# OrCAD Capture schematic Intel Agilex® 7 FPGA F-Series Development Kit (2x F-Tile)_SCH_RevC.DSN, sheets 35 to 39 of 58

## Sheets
35 PG38 I2C TRANSLATORS: size C
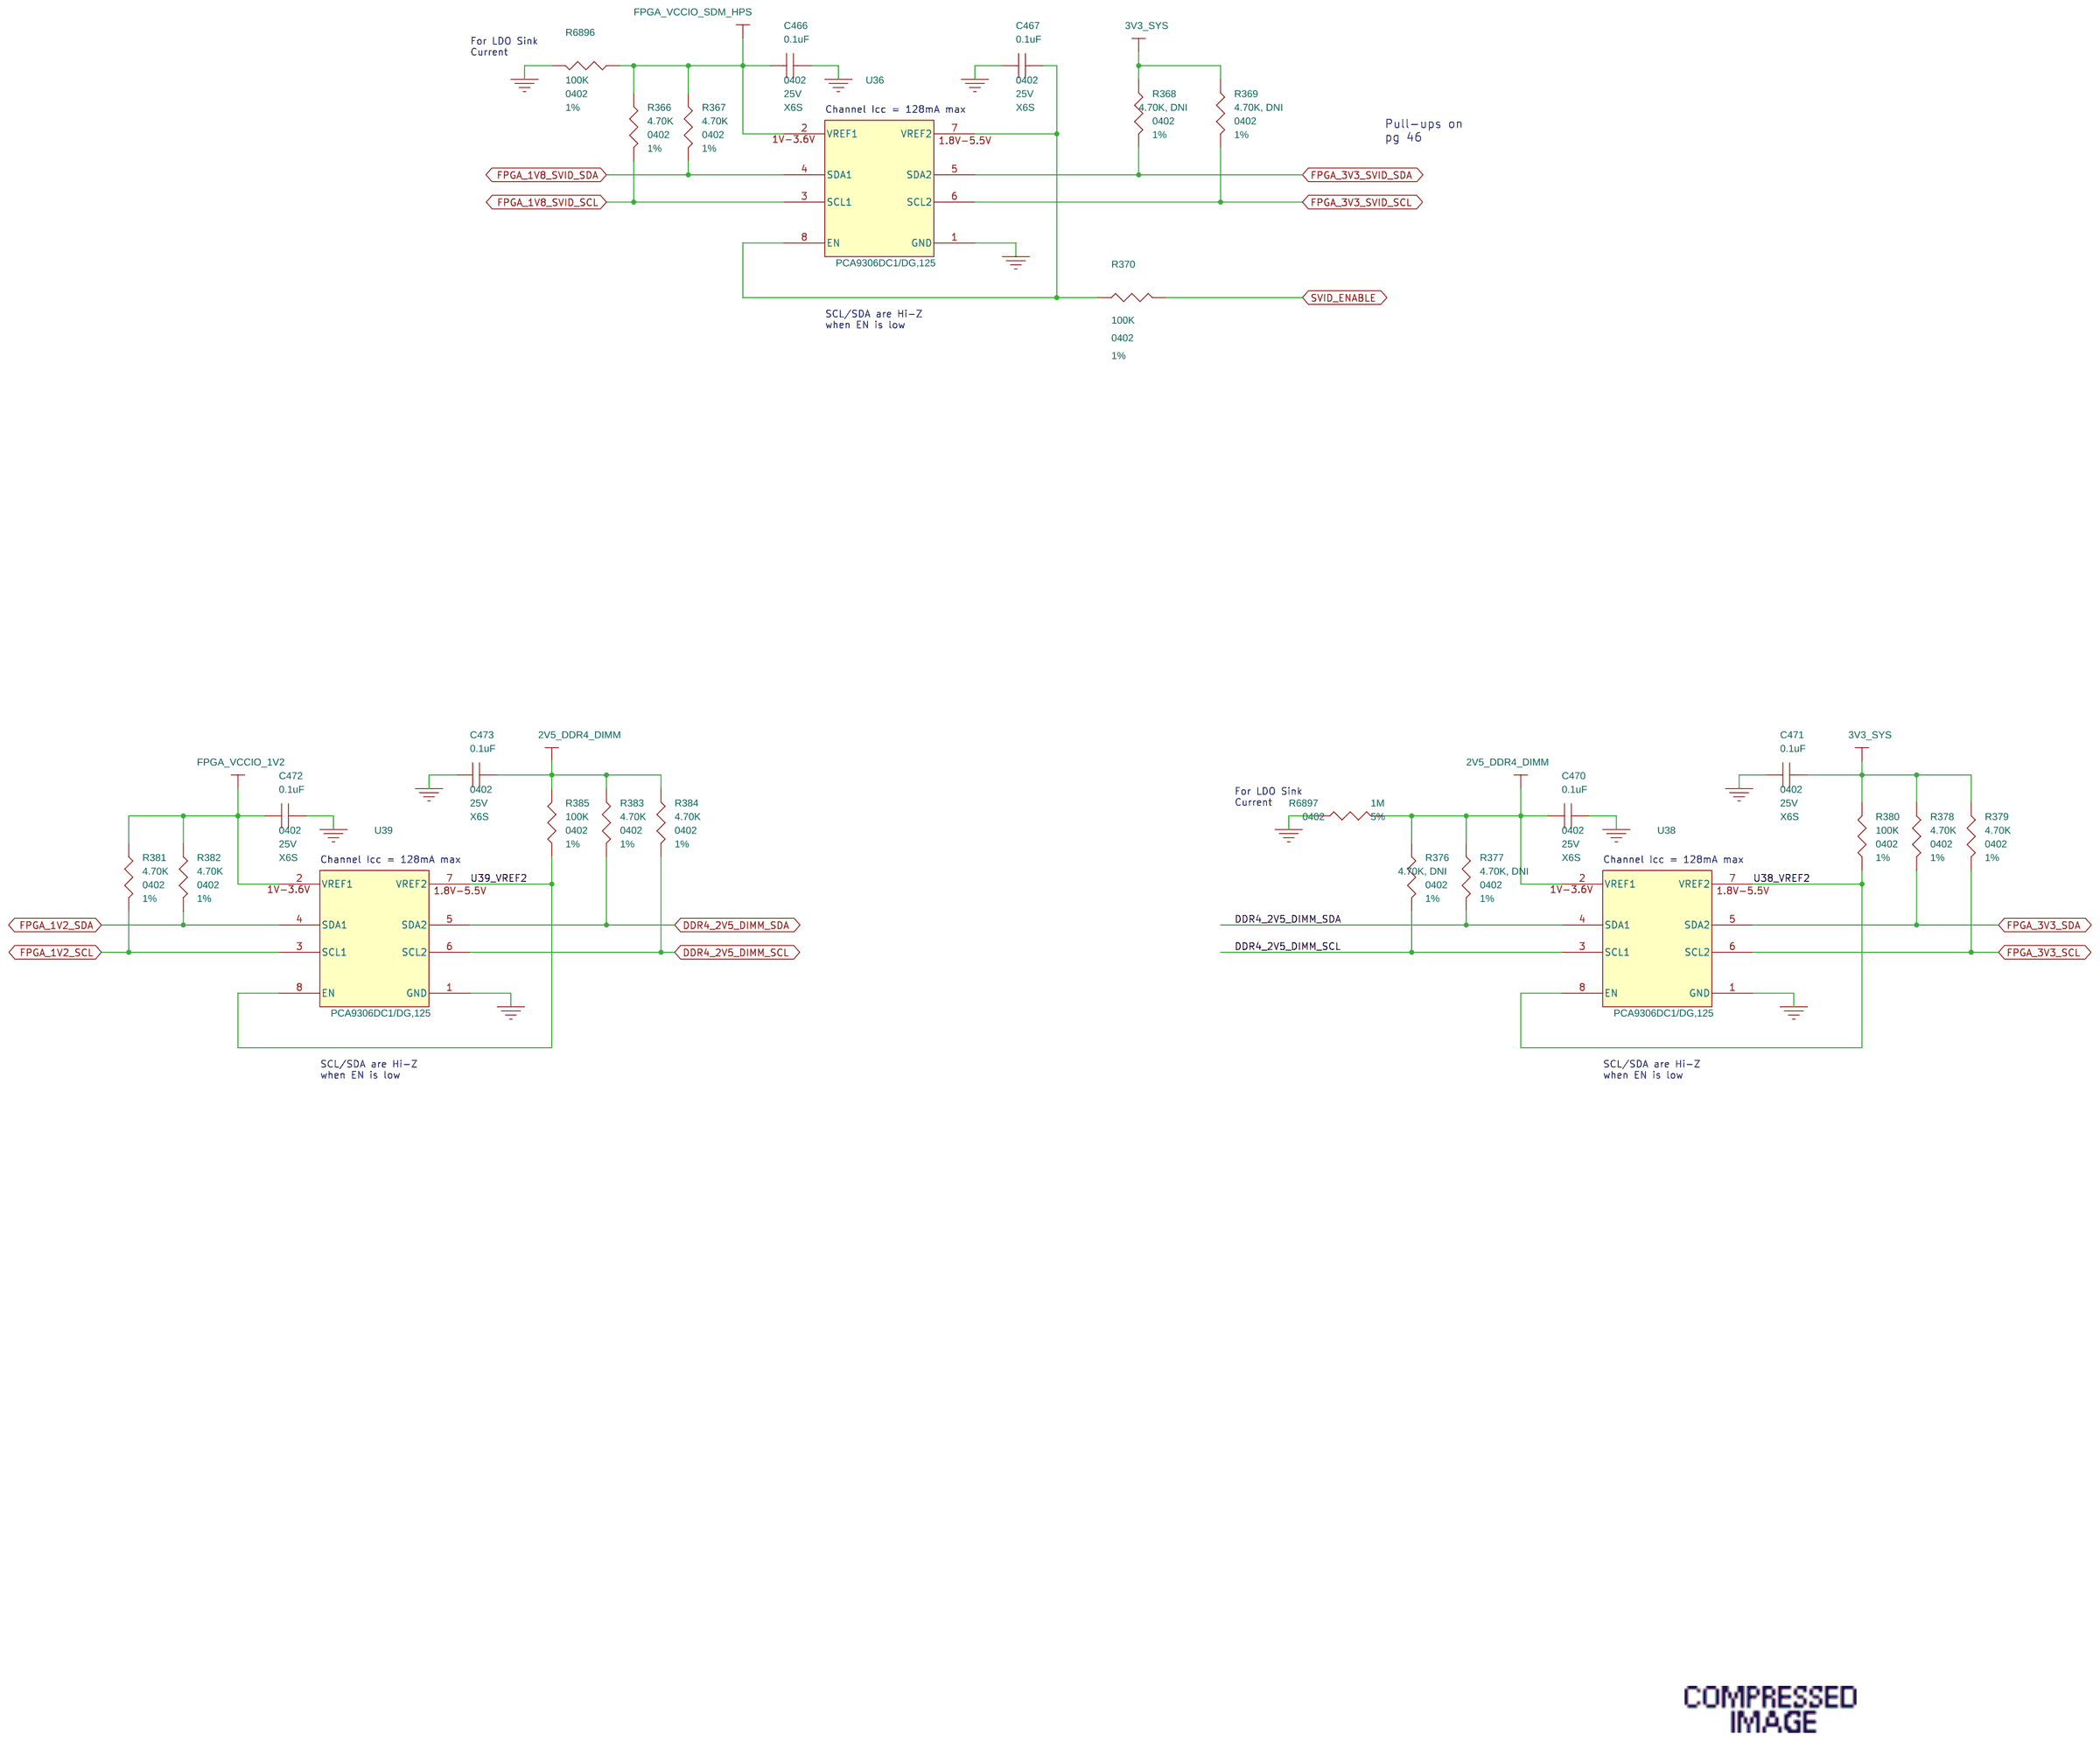
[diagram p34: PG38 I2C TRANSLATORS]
36 PG39 BUTTONS, SWITCHES, LEDS: size C
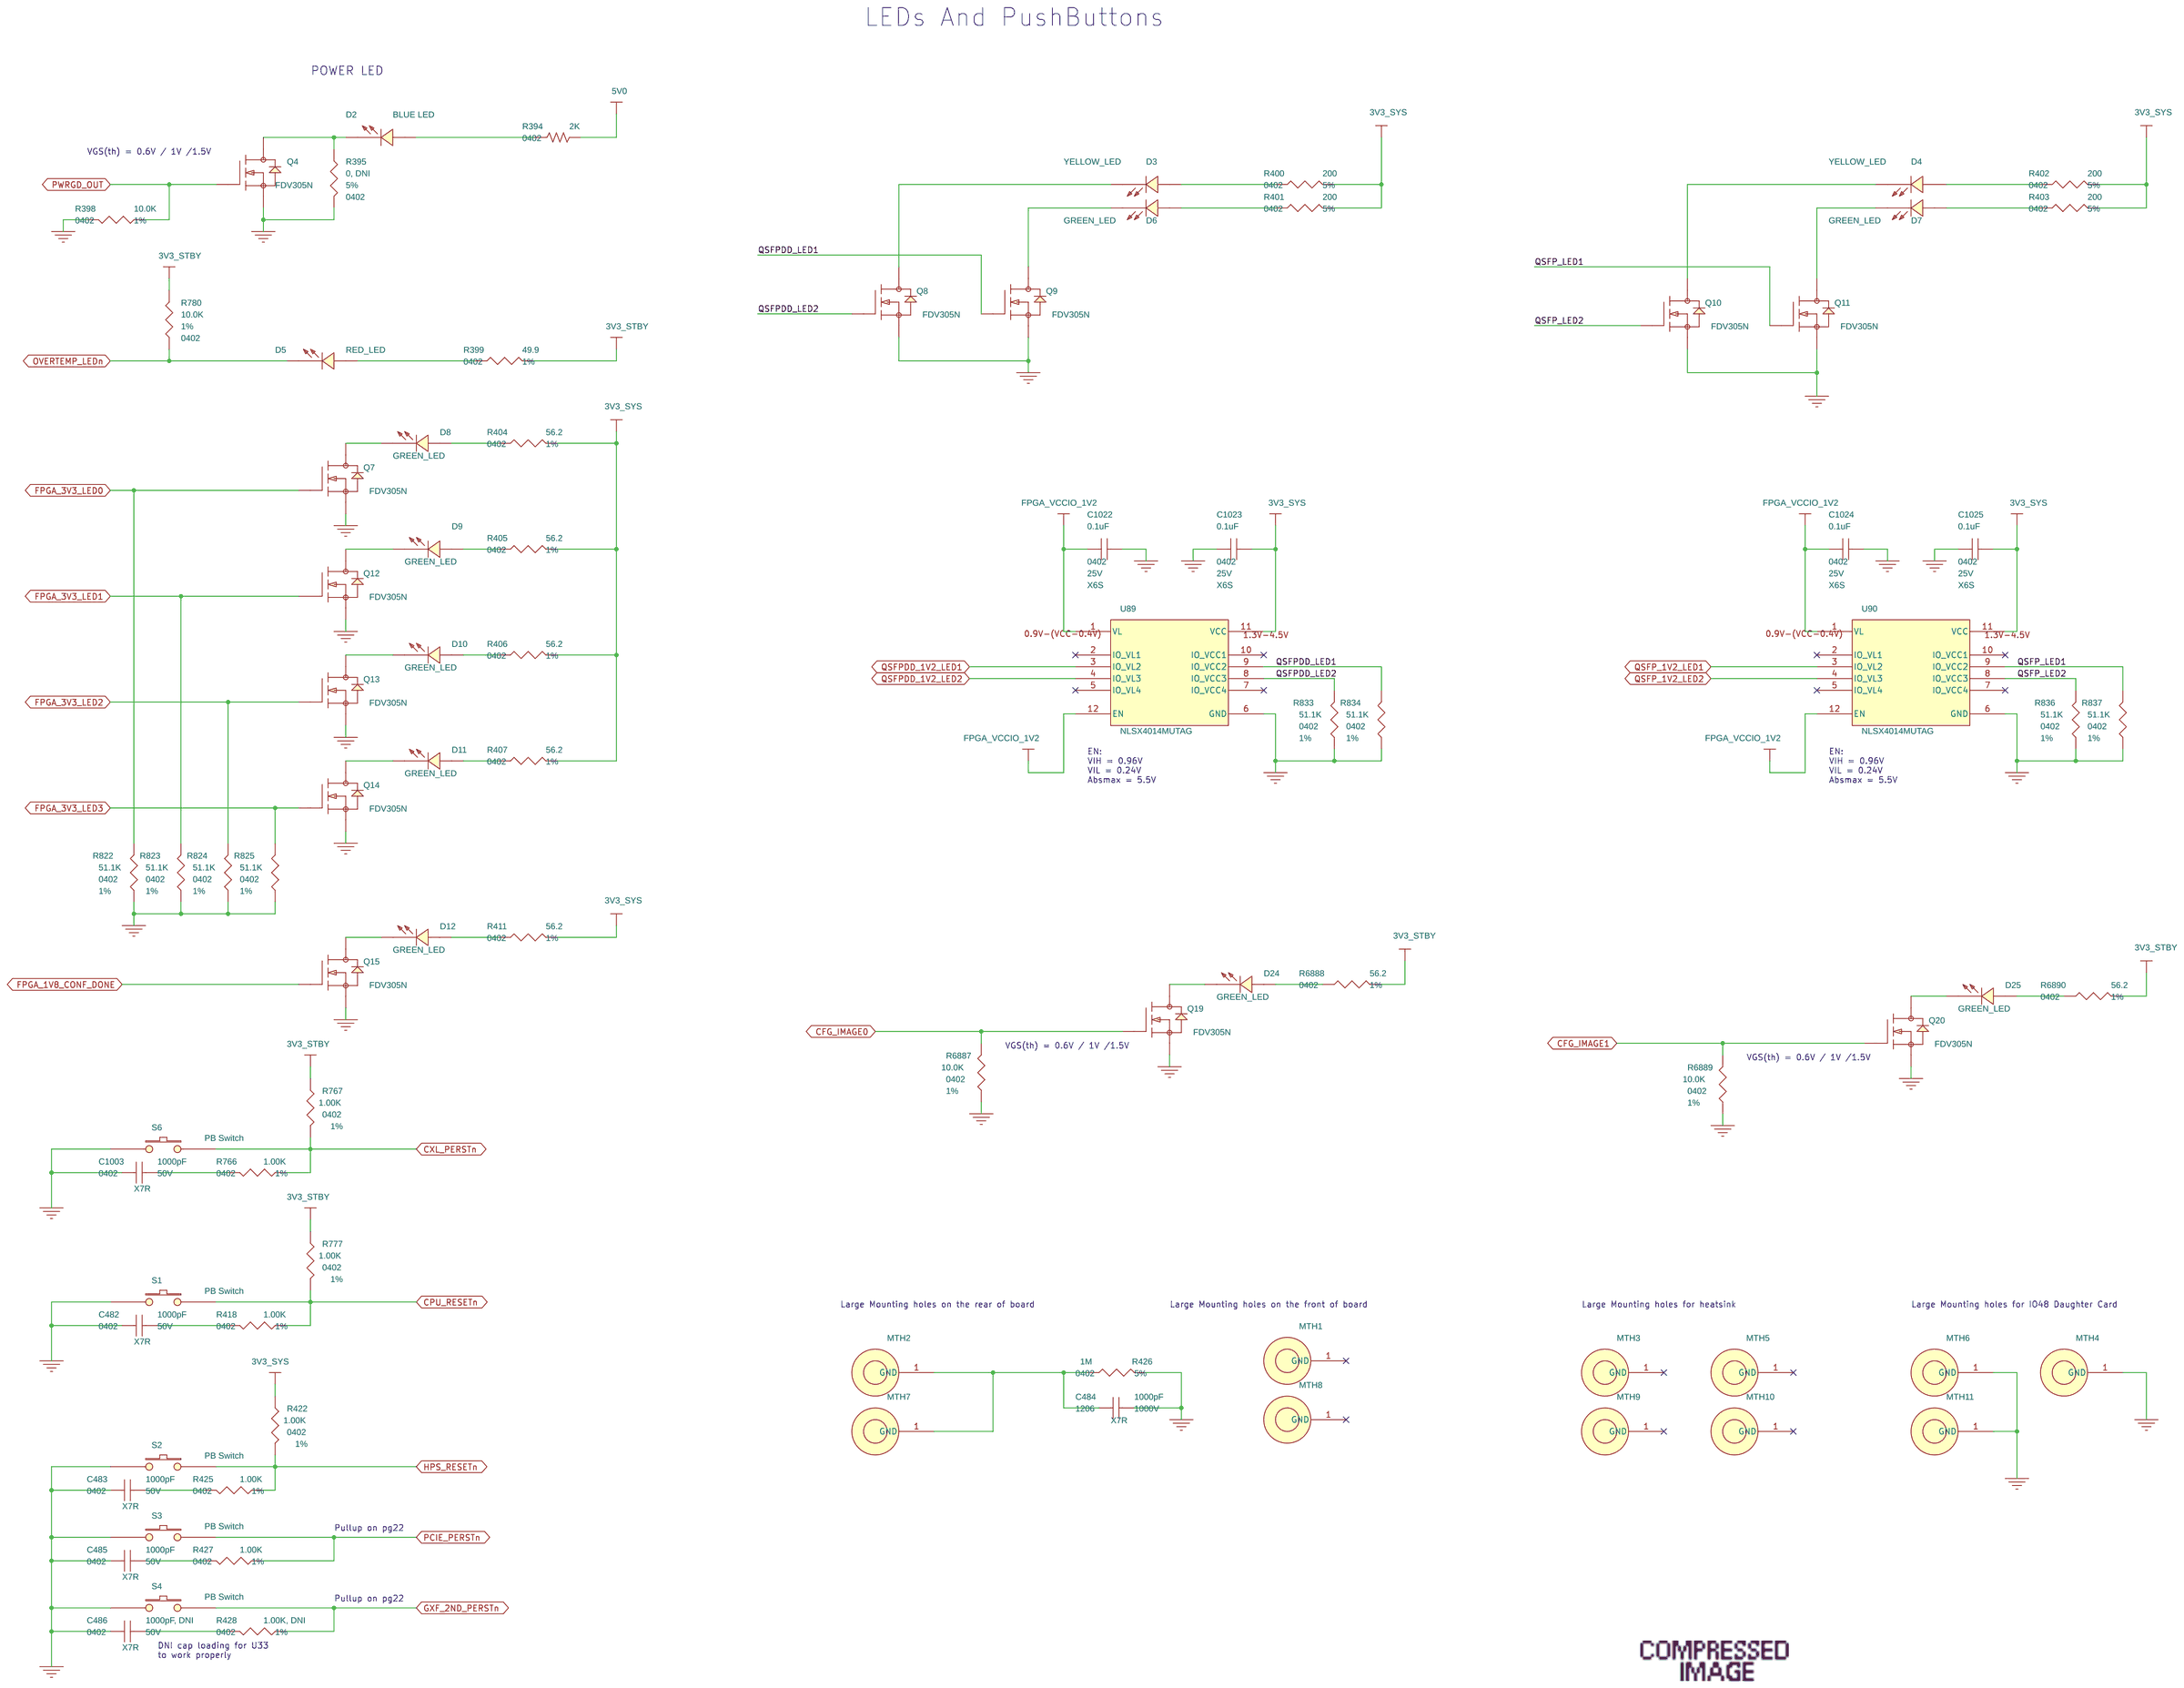
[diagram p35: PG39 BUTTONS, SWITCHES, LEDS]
37 PG40 EEPROM, NIOS FLASH: size C
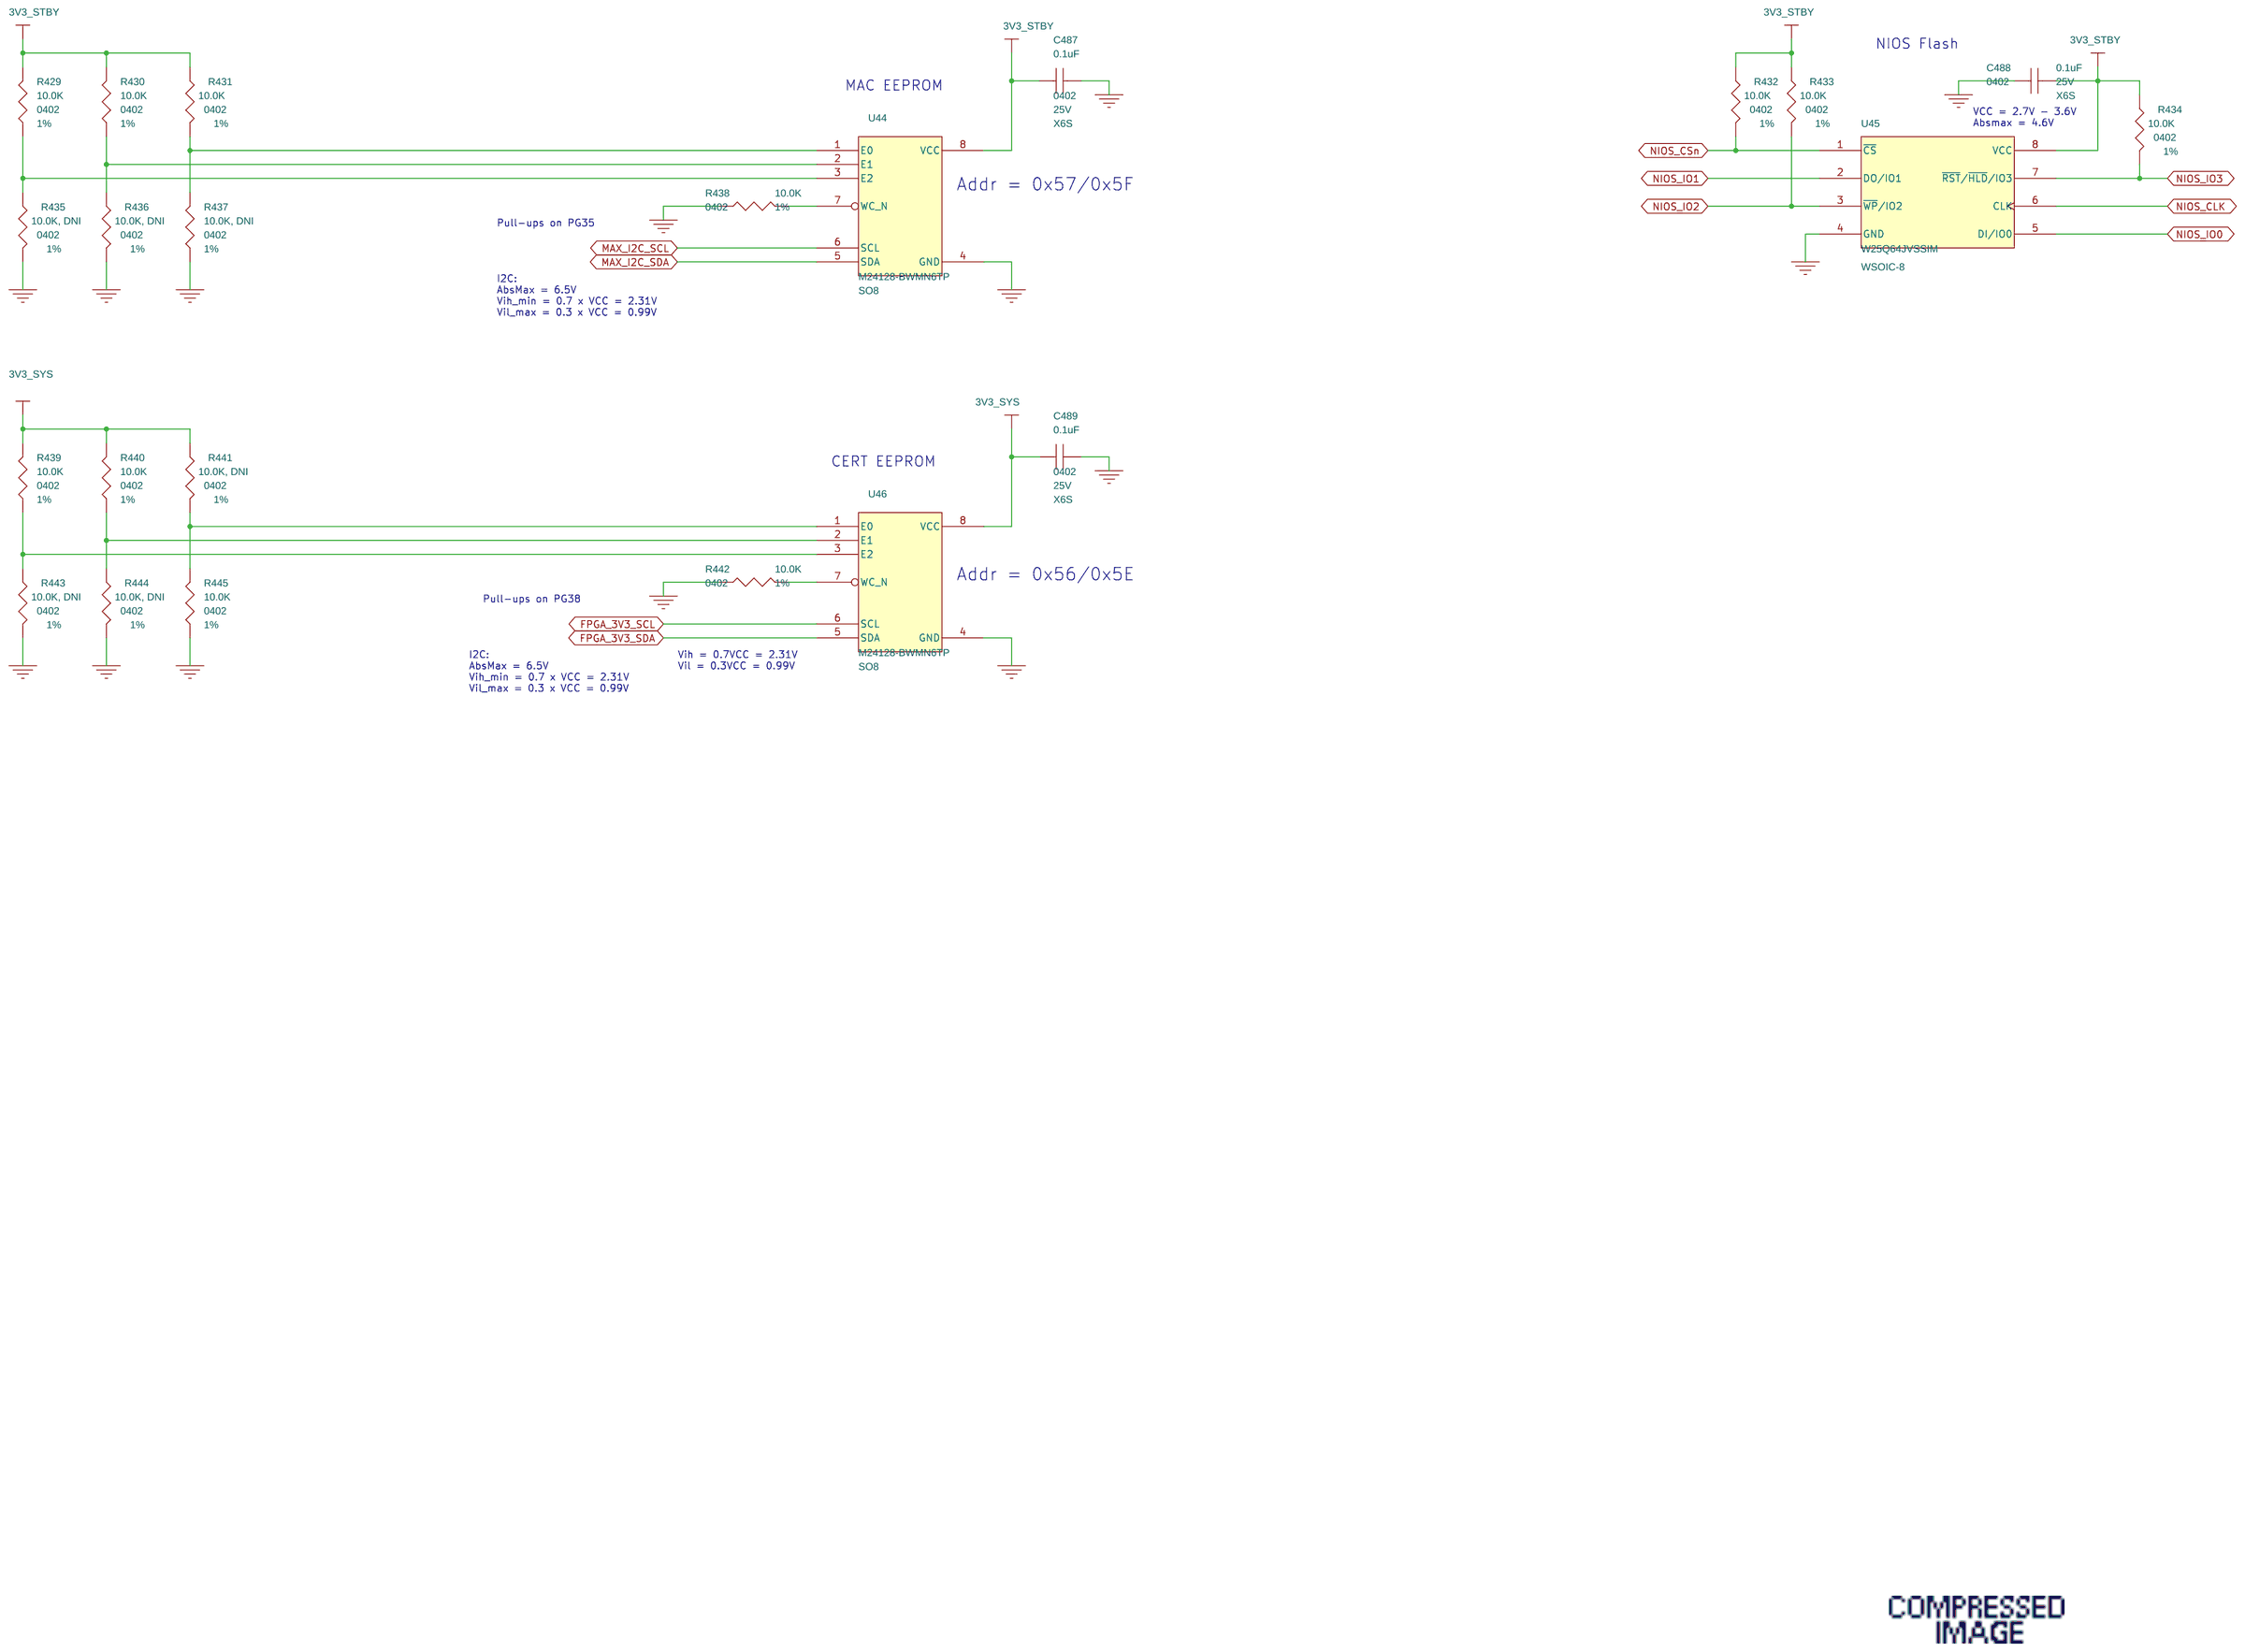
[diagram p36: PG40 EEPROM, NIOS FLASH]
38 PG41 USB BLASTER, JTAG: size C
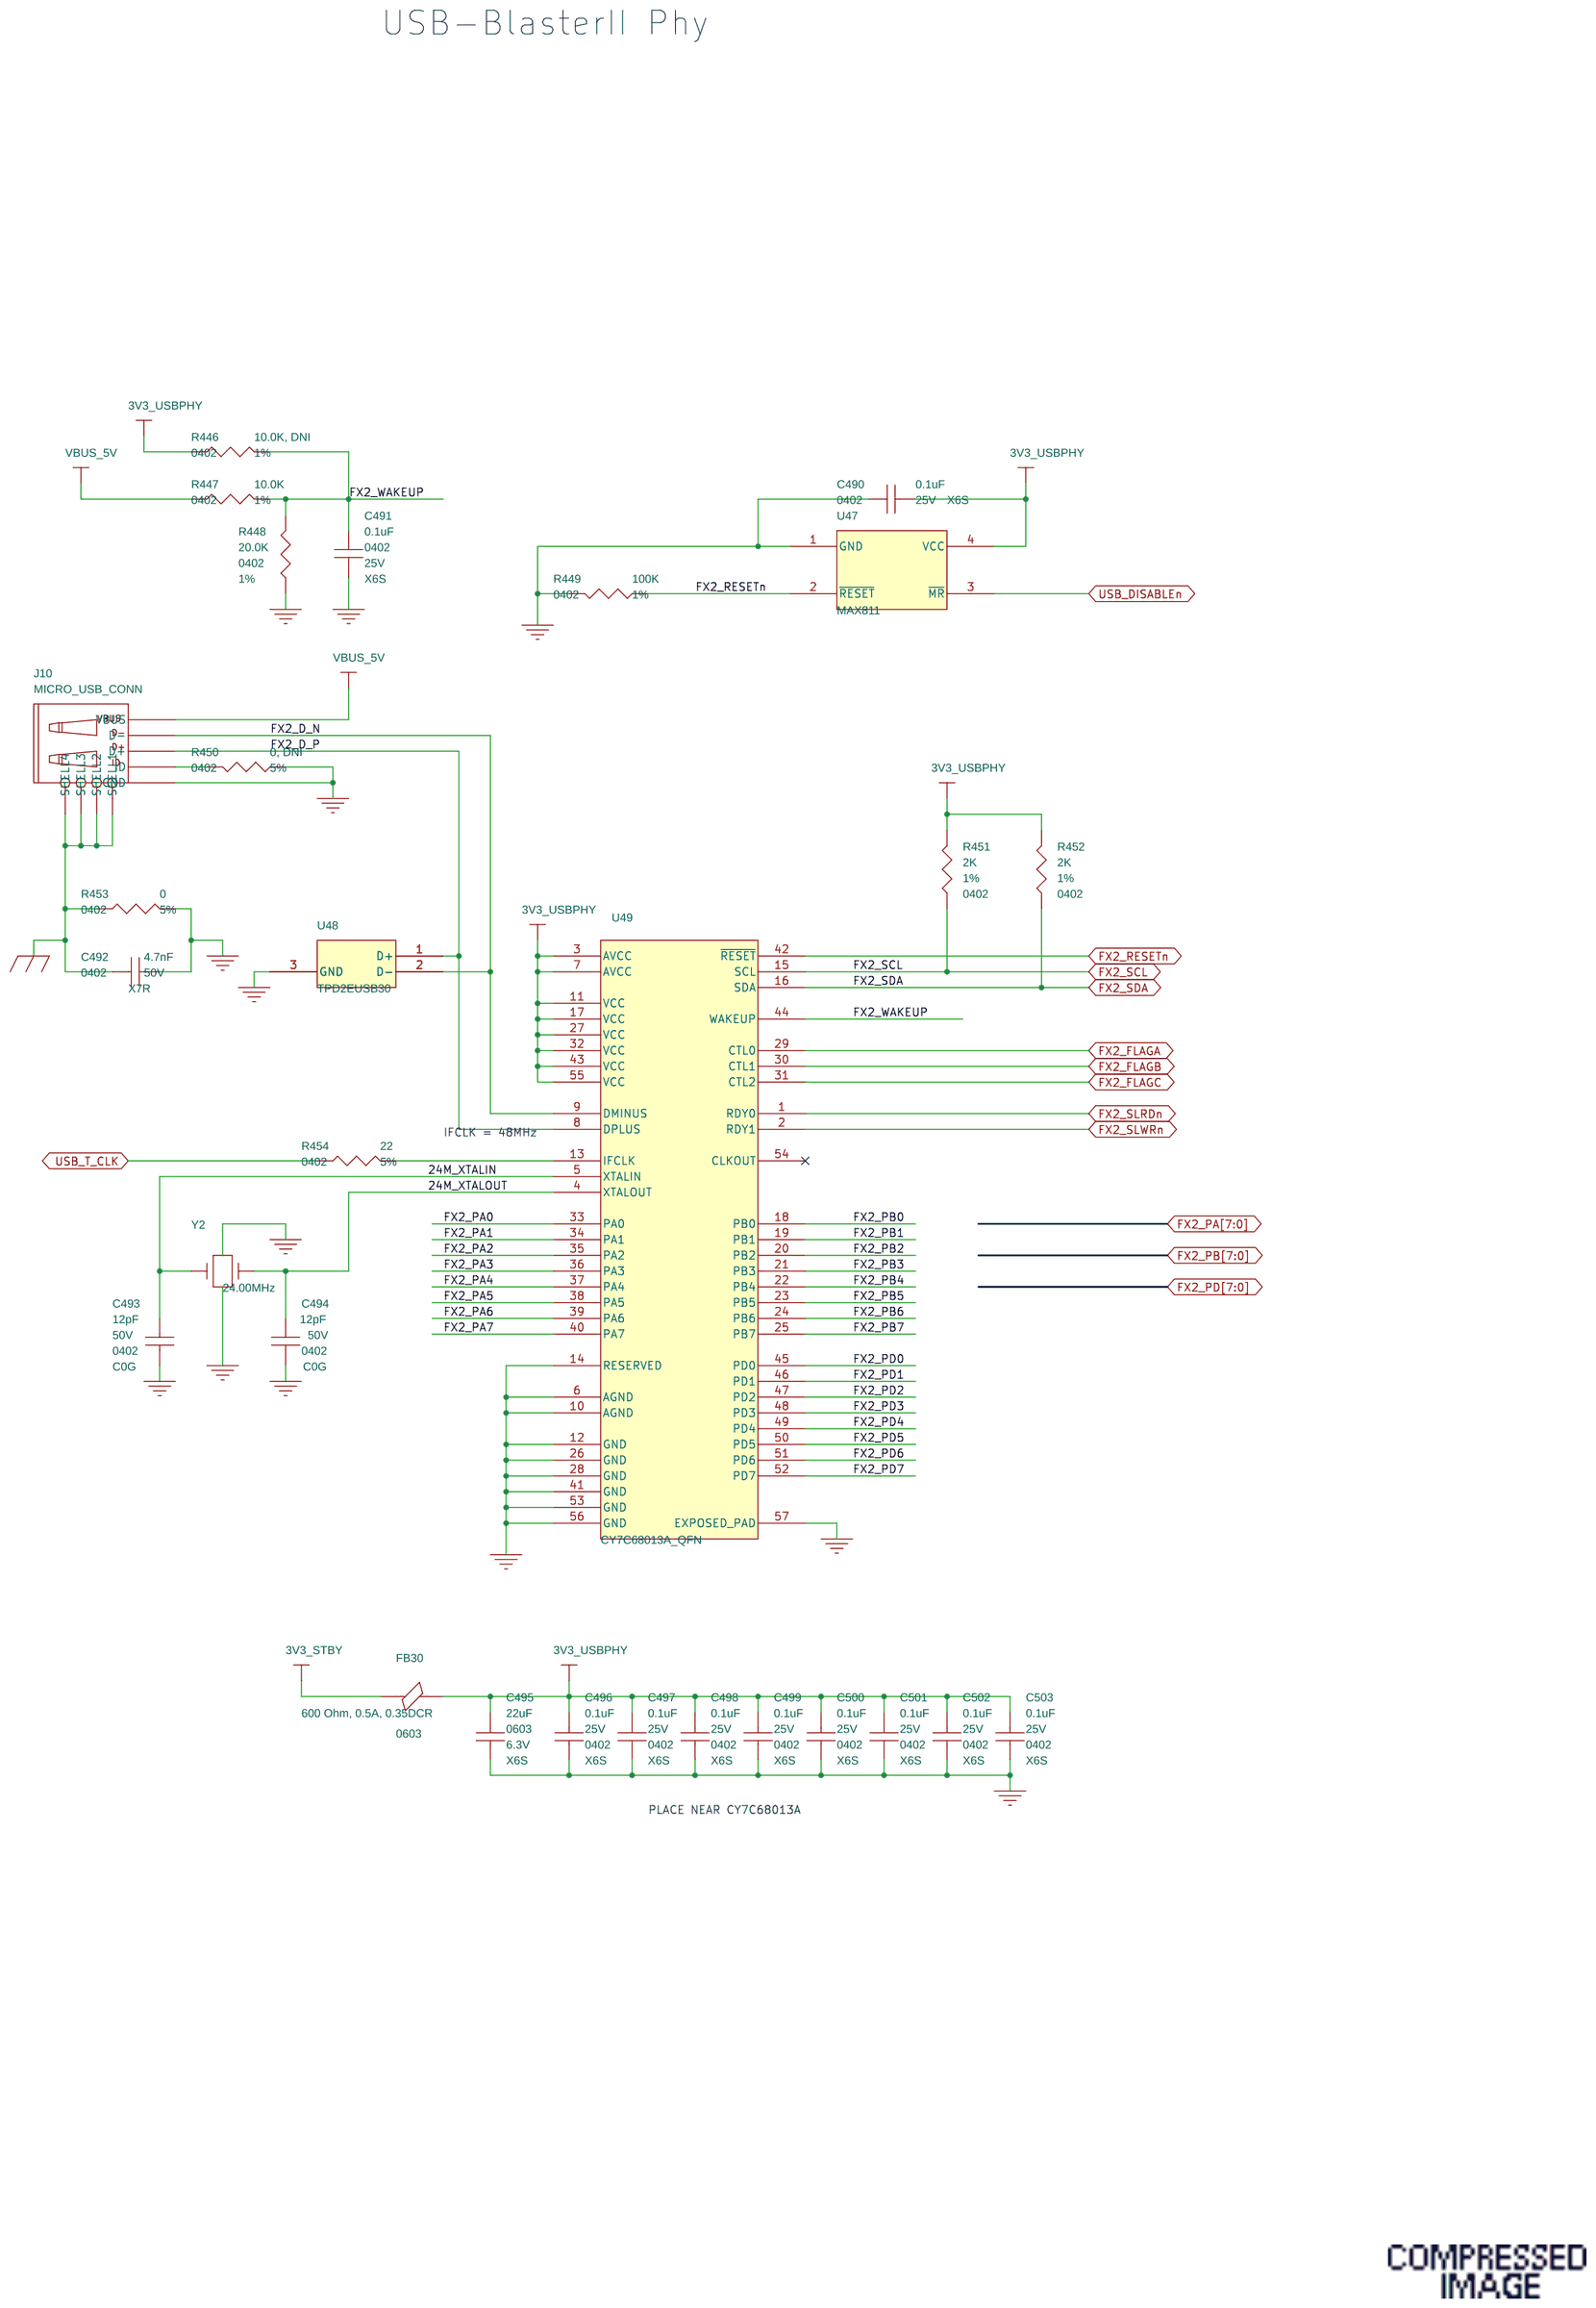
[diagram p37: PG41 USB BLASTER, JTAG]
39 PG42 FPGA DECAPS: size C
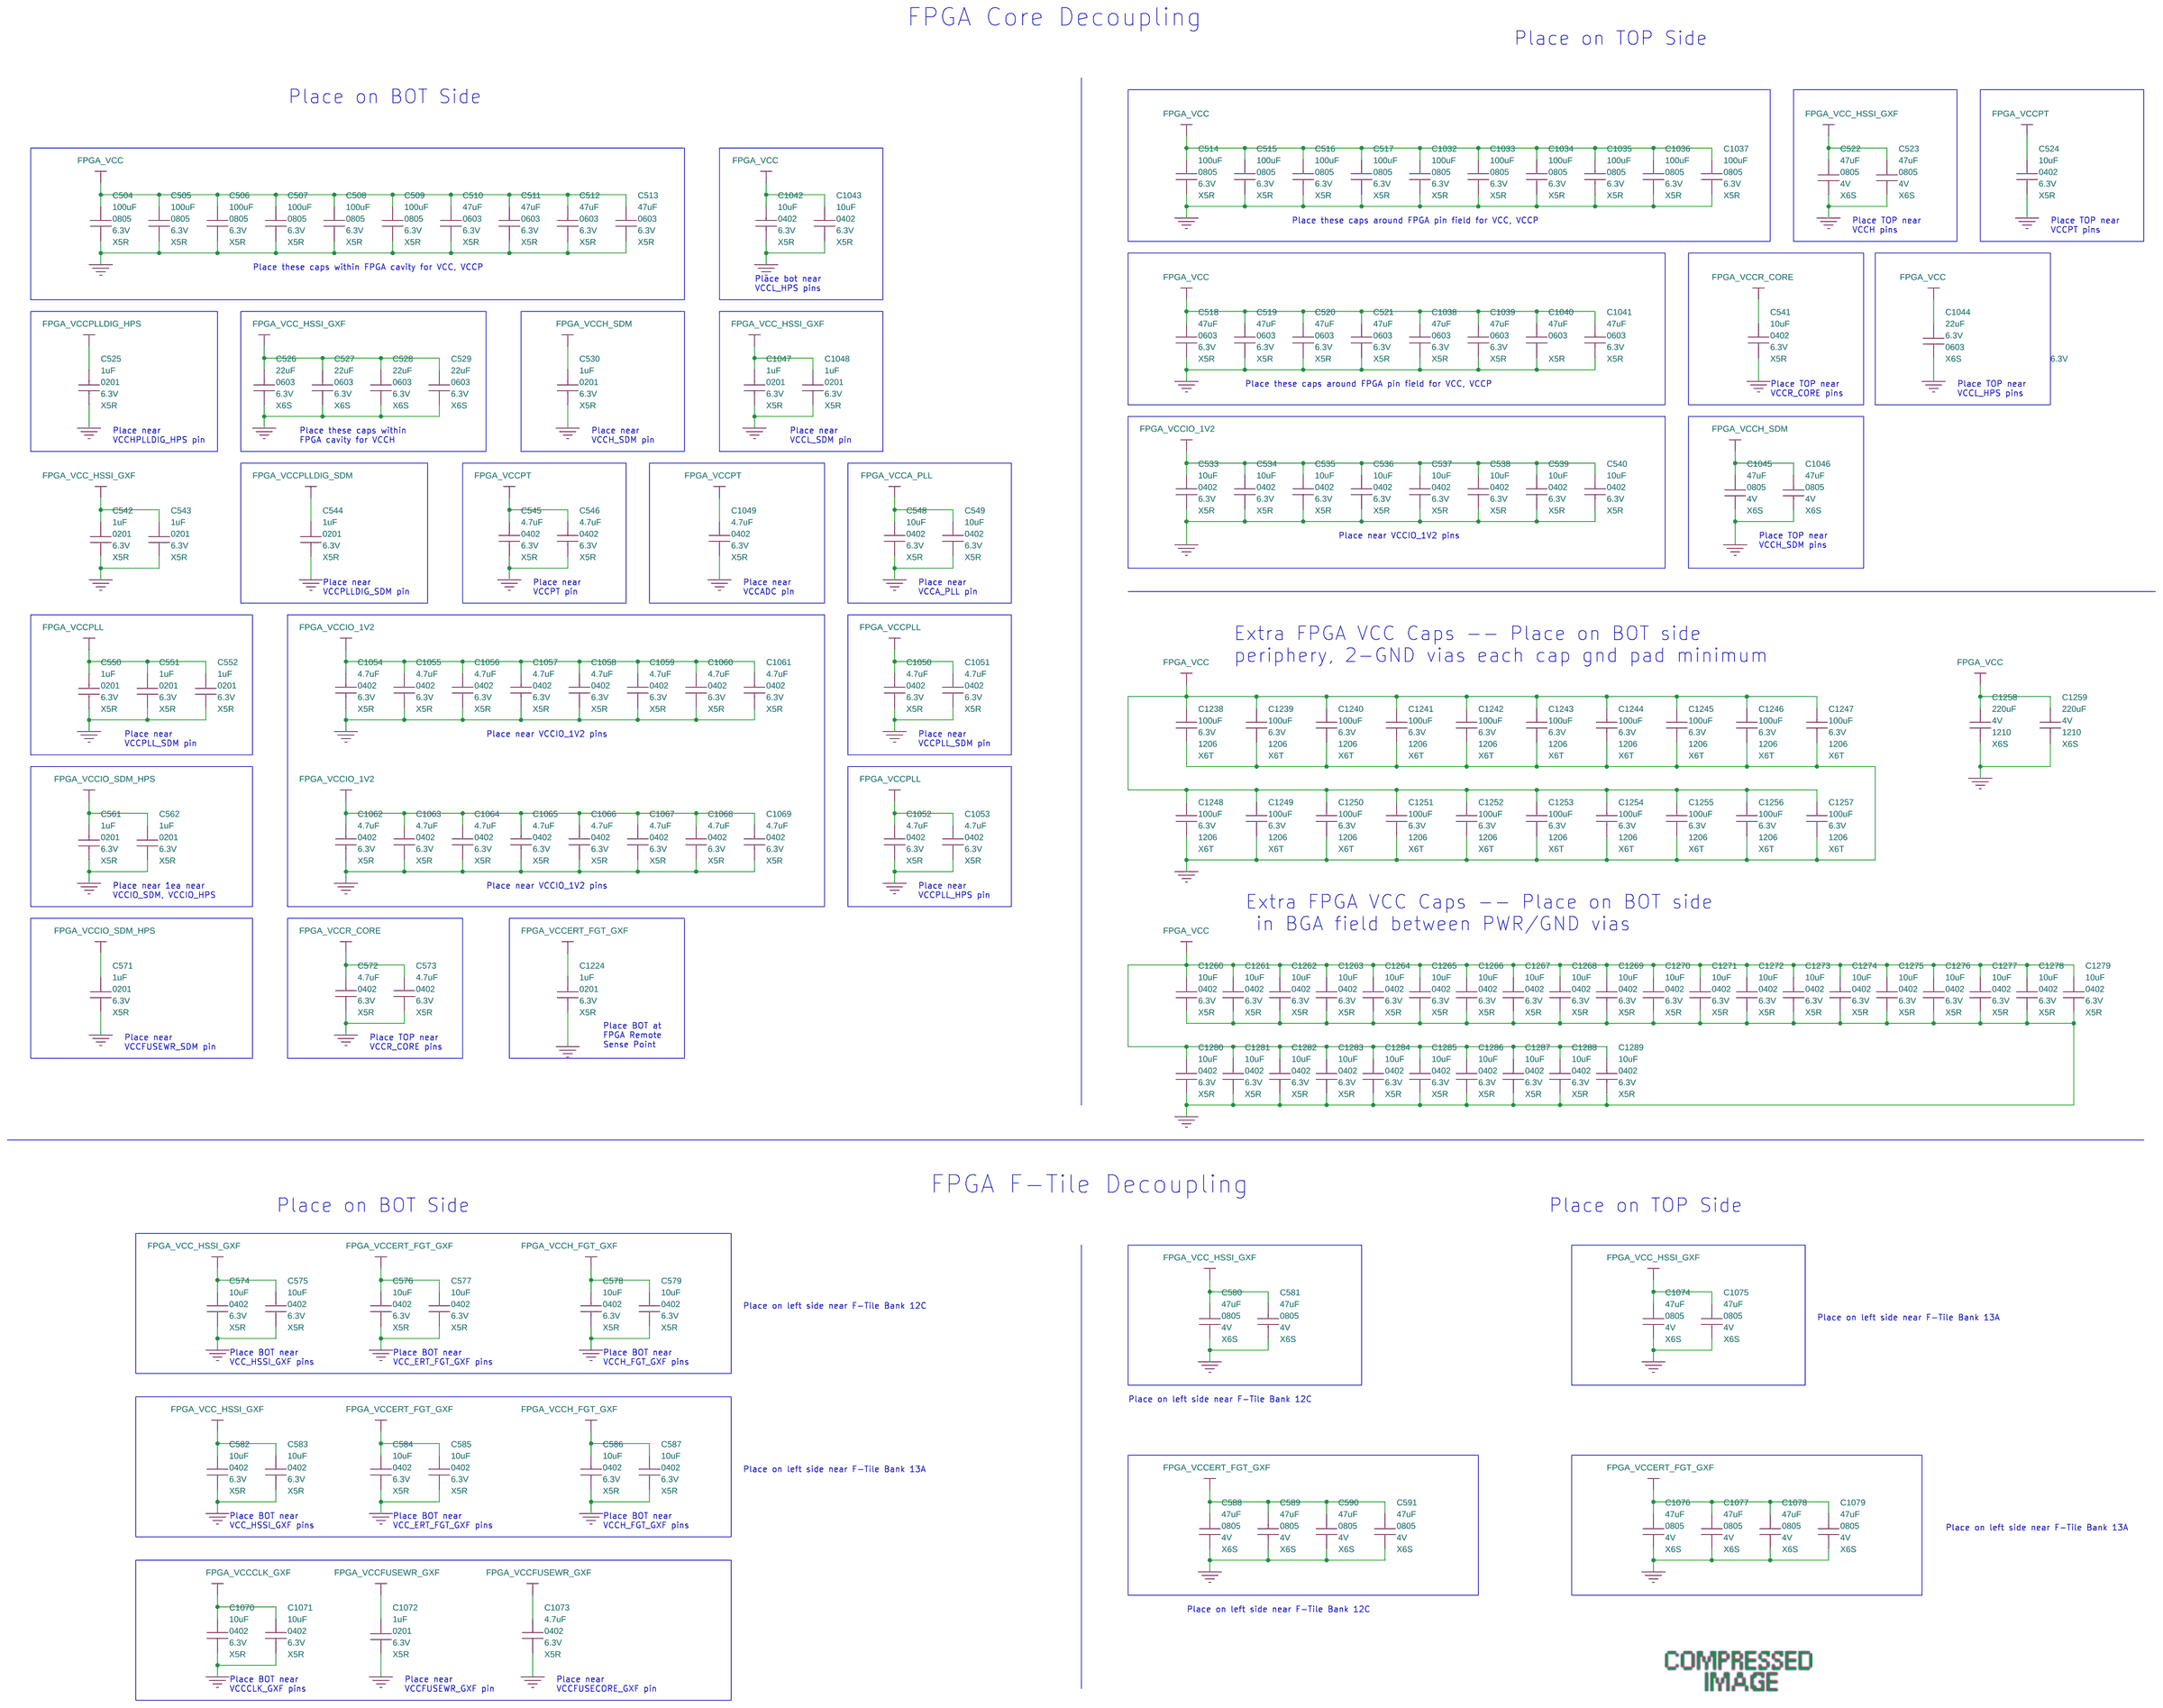
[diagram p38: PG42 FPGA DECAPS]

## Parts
sheet PG38 I2C TRANSLATORS
C466  0.1uF  [0402]
C467  0.1uF  [0402]
C470  0.1uF  [0402]
C471  0.1uF  [0402]
C472  0.1uF  [0402]
C473  0.1uF  [0402]
R366  4.70K  [0402]
R367  4.70K  [0402]
R368  4.70K, DNI  [0402]
R369  4.70K, DNI  [0402]
R370  100K  [0402]
R376  4.70K, DNI  [0402]
R377  4.70K, DNI  [0402]
R378  4.70K  [0402]
R379  4.70K  [0402]
R380  100K  [0402]
R381  4.70K  [0402]
R382  4.70K  [0402]
R383  4.70K  [0402]
R384  4.70K  [0402]
R385  100K  [0402]
R6896  100K  [0402]
R6897  1M  [0402]
U36  PCA9306DC1/DG,125  [VSSOP8]
U38  PCA9306DC1/DG,125  [VSSOP8]
U39  PCA9306DC1/DG,125  [VSSOP8]
sheet PG39 BUTTONS, SWITCHES, LEDS
C482  1000pF  [0402]
C483  1000pF  [0402]
C484  1000pF  [1206]
C485  1000pF  [0402]
C486  1000pF, DNI  [0402]
C1003  1000pF  [0402]
C1022  0.1uF  [0402]
C1023  0.1uF  [0402]
C1024  0.1uF  [0402]
C1025  0.1uF  [0402]
D2  BLUE LED  [LED_0603]
D3  YELLOW_LED  [LED_0603]
D4  YELLOW_LED  [LED_0603]
D5  RED_LED  [LED_0603]
D6  GREEN_LED  [LED_0603]
D7  GREEN_LED  [LED_0603]
D8  GREEN_LED  [LED_0603]
D9  GREEN_LED  [LED_0603]
D10  GREEN_LED  [LED_0603]
D11  GREEN_LED  [LED_0603]
D12  GREEN_LED  [LED_0603]
D24  GREEN_LED  [LED_0603]
D25  GREEN_LED  [LED_0603]
MTH1  MT_HOLE_GND  [MH_D125C175T_TB315]
MTH2  MT_HOLE_GND  [MH_D125C175T_TB315]
MTH3  MT_HOLE_GND  [MH_PTH_3_8MM]
MTH4  MT_HOLE_GND  [MTH250R125]
MTH5  MT_HOLE_GND  [MH_PTH_3_8MM]
MTH6  MT_HOLE_GND  [MTH250R125]
MTH7  MT_HOLE_GND  [MH_D125C175T_TB315]
MTH8  MT_HOLE_GND  [MH_D125C175T_TB315]
MTH9  MT_HOLE_GND  [MH_PTH_3_8MM]
MTH10  MT_HOLE_GND  [MH_PTH_3_8MM]
MTH11  MT_HOLE_GND  [MTH250R125]
Q4  FDV305N  [SOT23]
Q7  FDV305N  [SOT23]
Q8  FDV305N  [SOT23]
Q9  FDV305N  [SOT23]
Q10  FDV305N  [SOT23]
Q11  FDV305N  [SOT23]
Q12  FDV305N  [SOT23]
Q13  FDV305N  [SOT23]
Q14  FDV305N  [SOT23]
Q15  FDV305N  [SOT23]
Q19  FDV305N  [SOT23]
Q20  FDV305N  [SOT23]
R394  2K  [0402]
R395  0, DNI  [0402]
R398  10.0K  [0402]
R399  49.9  [0402]
R400  200  [0402]
R401  200  [0402]
R402  200  [0402]
R403  200  [0402]
R404  56.2  [0402]
R405  56.2  [0402]
R406  56.2  [0402]
R407  56.2  [0402]
R411  56.2  [0402]
R418  1.00K  [0402]
R422  1.00K  [0402]
R425  1.00K  [0402]
R426  1M  [0402]
R427  1.00K  [0402]
R428  1.00K, DNI  [0402]
R766  1.00K  [0402]
R767  1.00K  [0402]
R777  1.00K  [0402]
R780  10.0K  [0402]
R822  51.1K  [0402]
R823  51.1K  [0402]
R824  51.1K  [0402]
R825  51.1K  [0402]
R833  51.1K  [0402]
R834  51.1K  [0402]
R836  51.1K  [0402]
R837  51.1K  [0402]
R6887  10.0K  [0402]
R6888  56.2  [0402]
R6889  10.0K  [0402]
R6890  56.2  [0402]
S1  PB Switch  [WURTH_6X3P5_TACT_SWITCH]
S2  PB Switch  [WURTH_6X3P5_TACT_SWITCH]
S3  PB Switch  [WURTH_6X3P5_TACT_SWITCH]
S4  PB Switch  [WURTH_6X3P5_TACT_SWITCH]
S6  PB Switch  [WURTH_6X3P5_TACT_SWITCH]
U89  NLSX4014MUTAG  [UQFN12]
U90  NLSX4014MUTAG  [UQFN12]
sheet PG40 EEPROM, NIOS FLASH
C487  0.1uF  [0402]
C488  0.1uF  [0402]
C489  0.1uF  [0402]
R429  10.0K  [0402]
R430  10.0K  [0402]
R431  10.0K  [0402]
R432  10.0K  [0402]
R433  10.0K  [0402]
R434  10.0K  [0402]
R435  10.0K, DNI  [0402]
R436  10.0K, DNI  [0402]
R437  10.0K, DNI  [0402]
R438  10.0K  [0402]
R439  10.0K  [0402]
R440  10.0K  [0402]
R441  10.0K, DNI  [0402]
R442  10.0K  [0402]
R443  10.0K, DNI  [0402]
R444  10.0K, DNI  [0402]
R445  10.0K  [0402]
U44  M24128-BWMN6TP  [SO8]
U45  W25Q64JVSSIM  [WSOIC-8]
U46  M24128-BWMN6TP  [SO8]
sheet PG41 USB BLASTER, JTAG
C490  0.1uF  [0402]
C491  0.1uF  [0402]
C492  4.7nF  [0402]
C493  12pF  [0402]
C494  12pF  [0402]
C495  22uF  [0603]
C496  0.1uF  [0402]
C497  0.1uF  [0402]
C498  0.1uF  [0402]
C499  0.1uF  [0402]
C500  0.1uF  [0402]
C501  0.1uF  [0402]
C502  0.1uF  [0402]
C503  0.1uF  [0402]
FB30  600 Ohm, 0.5A, 0.35DCR  [0603]
J10  MICRO_USB_CONN  [molex-micro-usb-47589-001]
R446  10.0K, DNI  [0402]
R447  10.0K  [0402]
R448  20.0K  [0402]
R449  100K  [0402]
R450  0, DNI  [0402]
R451  2K  [0402]
R452  2K  [0402]
R453  0  [0402]
R454  22  [0402]
U47  MAX811  [SOT-143]
U48  TPD2EUSB30  [DRT]
U49  CY7C68013A_QFN  [QFN56]
Y2  24.00MHz  [XTAL_FA-128]
sheet PG42 FPGA DECAPS
C504  100uF  [0805]
C505  100uF  [0805]
C506  100uF  [0805]
C507  100uF  [0805]
C508  100uF  [0805]
C509  100uF  [0805]
C510  47uF  [0603]
C511  47uF  [0603]
C512  47uF  [0603]
C513  47uF  [0603]
C514  100uF  [0805]
C515  100uF  [0805]
C516  100uF  [0805]
C517  100uF  [0805]
C518  47uF  [0603]
C519  47uF  [0603]
C520  47uF  [0603]
C521  47uF  [0603]
C522  47uF  [0805]
C523  47uF  [0805]
C524  10uF  [0402]
C525  1uF  [0201]
C526  22uF  [0603]
C527  22uF  [0603]
C528  22uF  [0603]
C529  22uF  [0603]
C530  1uF  [0201]
C533  10uF  [0402]
C534  10uF  [0402]
C535  10uF  [0402]
C536  10uF  [0402]
C537  10uF  [0402]
C538  10uF  [0402]
C539  10uF  [0402]
C540  10uF  [0402]
C541  10uF  [0402]
C542  1uF  [0201]
C543  1uF  [0201]
C544  1uF  [0201]
C545  4.7uF  [0402]
C546  4.7uF  [0402]
C548  10uF  [0402]
C549  10uF  [0402]
C550  1uF  [0201]
C551  1uF  [0201]
C552  1uF  [0201]
C561  1uF  [0201]
C562  1uF  [0201]
C571  1uF  [0201]
C572  4.7uF  [0402]
C573  4.7uF  [0402]
C574  10uF  [0402]
C575  10uF  [0402]
C576  10uF  [0402]
C577  10uF  [0402]
C578  10uF  [0402]
C579  10uF  [0402]
C580  47uF  [0805]
C581  47uF  [0805]
C582  10uF  [0402]
C583  10uF  [0402]
C584  10uF  [0402]
C585  10uF  [0402]
C586  10uF  [0402]
C587  10uF  [0402]
C588  47uF  [0805]
C589  47uF  [0805]
C590  47uF  [0805]
C591  47uF  [0805]
C1032  100uF  [0805]
C1033  100uF  [0805]
C1034  100uF  [0805]
C1035  100uF  [0805]
C1036  100uF  [0805]
C1037  100uF  [0805]
C1038  47uF  [0603]
C1039  47uF  [0603]
C1040  47uF  [0603]
C1041  47uF  [0603]
C1042  10uF  [0402]
C1043  10uF  [0402]
C1044  22uF  [0603]
C1045  47uF  [0805]
C1046  47uF  [0805]
C1047  1uF  [0201]
C1048  1uF  [0201]
C1049  4.7uF  [0402]
C1050  4.7uF  [0402]
C1051  4.7uF  [0402]
C1052  4.7uF  [0402]
C1053  4.7uF  [0402]
C1054  4.7uF  [0402]
C1055  4.7uF  [0402]
C1056  4.7uF  [0402]
C1057  4.7uF  [0402]
C1058  4.7uF  [0402]
C1059  4.7uF  [0402]
C1060  4.7uF  [0402]
C1061  4.7uF  [0402]
C1062  4.7uF  [0402]
C1063  4.7uF  [0402]
C1064  4.7uF  [0402]
C1065  4.7uF  [0402]
C1066  4.7uF  [0402]
C1067  4.7uF  [0402]
C1068  4.7uF  [0402]
C1069  4.7uF  [0402]
C1070  10uF  [0402]
C1071  10uF  [0402]
C1072  1uF  [0201]
C1073  4.7uF  [0402]
C1074  47uF  [0805]
C1075  47uF  [0805]
C1076  47uF  [0805]
C1077  47uF  [0805]
C1078  47uF  [0805]
C1079  47uF  [0805]
C1224  1uF  [0201]
C1238  100uF  [1206]
C1239  100uF  [1206]
C1240  100uF  [1206]
C1241  100uF  [1206]
C1242  100uF  [1206]
C1243  100uF  [1206]
C1244  100uF  [1206]
C1245  100uF  [1206]
C1246  100uF  [1206]
C1247  100uF  [1206]
C1248  100uF  [1206]
C1249  100uF  [1206]
C1250  100uF  [1206]
C1251  100uF  [1206]
C1252  100uF  [1206]
C1253  100uF  [1206]
C1254  100uF  [1206]
C1255  100uF  [1206]
C1256  100uF  [1206]
C1257  100uF  [1206]
C1258  220uF  [1210]
C1259  220uF  [1210]
C1260  10uF  [0402]
C1261  10uF  [0402]
C1262  10uF  [0402]
C1263  10uF  [0402]
C1264  10uF  [0402]
C1265  10uF  [0402]
C1266  10uF  [0402]
C1267  10uF  [0402]
C1268  10uF  [0402]
C1269  10uF  [0402]
C1270  10uF  [0402]
C1271  10uF  [0402]
C1272  10uF  [0402]
C1273  10uF  [0402]
C1274  10uF  [0402]
C1275  10uF  [0402]
C1276  10uF  [0402]
C1277  10uF  [0402]
C1278  10uF  [0402]
C1279  10uF  [0402]
C1280  10uF  [0402]
C1281  10uF  [0402]
C1282  10uF  [0402]
C1283  10uF  [0402]
C1284  10uF  [0402]
C1285  10uF  [0402]
C1286  10uF  [0402]
C1287  10uF  [0402]
C1288  10uF  [0402]
C1289  10uF  [0402]

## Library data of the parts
C466 C467 C470-C473 C487-C491 C496-C503 C1022-C1025 = CAP: CAP CER 0.1UF 25V X6S 0402; Dielectric: X6S; IPN: K19434-001; Item Num: K19434-001; LIFECYCLE_PHASE: Active; Lead Free Status: Lead Free; MFR_LIFECYCLE: Active; Manufacturer: Murata; Manufacturer Part Num: GRM155C81E104KA12D; Num Pins: 2; PART_SUBCLASS: CAPACITORS; Part Class: CAPACITORS; RATED_VOLTAGE: 25V; RoHS Compliant: RoHS Compliant; Temperature Coefficient: X6S; Tolerance: 10%
R366-R369 R376-R379 R381-R384 = RESISTOR: RES,4.70K OHMS,1.0%,1/16W,0402; AGILE_LINK: http://sj-agile9app/Agile/PLMServlet?action=OpenEmailObject&classid=10000&objid=146753272; Item Num: A93548-517; LIFECYCLE_PHASE: Active; Lead Free Status: Yes; MFR_LIFECYCLE: Active; Manufacturer: Vishay; Manufacturer Part Num: CRCW04024K70FKED; Num Pins: 2; PART_SUBCLASS: RESISTORS; POWER: 1/16W; RESISTANCE: 4.7K; RoHS Compliant: Yes; TOLERANCE: 1%
R370 R380 R385 R449 R6896 = RESISTOR: RES,100K OHMS,1.0%,1/16W,0402; Item Num: A78422-001; Lead Free Status: Yes; Manufacturer: Panasonic; Manufacturer Part Num: ERJ-2RKF1003X; Num Pins: 2; Part Class: Resistors; RoHS Compliant: Yes; TOLERANCE: 1%
R426 R6897 = RESISTOR: RES,1M OHMS,5.0%,1/16W,0402; AGILE_LINK: http://sj-agile9app/Agile/PLMServlet?action=OpenEmailObject&classid=10000&objid=146548997; Item Num: K15866-001; LIFECYCLE_PHASE: Active; Lead Free Status: No; MFR_LIFECYCLE: Active; Manufacturer: Panasonic; Manufacturer Part Num: ERJ-2GEJ105X; Num Pins: 2; PART_SUBCLASS: RESISTORS; POWER: 1/16W; RoHS Compliant: Yes; TOLERANCE: 5%
U36 U38 U39 = PCA9306DC,125: IC, LIN, VSSOP, PCA9306; Item Num: E10432-001; Manufacturer: NXP
C482 C483 C485 C1003 = CAP: CAPC,X7R,0402,1000.000PF,50.000V,+/- 10%; Dielectric: X7R; Item Num: A36096-004; LIFECYCLE_PHASE: Active; Lead Free Status: Lead Free; Manufacturer: Yageo; Manufacturer Part Num: CC0402KRX7R9BB102; Num Pins: 2; Part Class: CAPACITORS; RATED_VOLTAGE: 50V; RoHS Compliant: RoHS Compliant; Temperature Coefficient: X7R; Tolerance: 10%
C484 = CAP: CAP CER 1000PF 1000V X7R 1206; AGILE_LINK: http://sj-agile9app/Agile/PLMServlet?action=OpenEmailObject&classid=10000&objid=215384813; Item Num: K13749-001; LIFECYCLE_PHASE: Active; Lead Free Status: Lead Free; MFR_LIFECYCLE: Active; Manufacturer: Murata; Manufacturer Part Num: GRM31BR73A102KW01L; Num Pins: 2; PACKAGING: Tape & Reel (TR); PART_SUBCLASS: CAPACITORS; RATED_VOLTAGE: 1000V; RoHS Compliant: RoHS Compliant; Supplier Part Num: GRM31BR73A102KW01L; Temperature Coefficient: X7R; Tolerance: +/-10%
C486 = CAP: CAPC,X7R,0402,1000.000PF,50.000V,+/- 10%; CAPACITANCE: 1000pF; Dielectric: X7R; Item Num: A36096-004; LIFECYCLE_PHASE: Active; Lead Free Status: Lead Free; Manufacturer: Yageo; Manufacturer Part Num: CC0402KRX7R9BB102; Num Pins: 2; Part Class: CAPACITORS; RATED_VOLTAGE: 50V; RoHS Compliant: RoHS Compliant; Temperature Coefficient: X7R; Tolerance: 10%
D2 = LED_0: LED - BLUE, VF = 3.2V, IF = 0.03A, 0603; Item Num: K15378-001; Lead Free Status: No; Manufacturer: Wurth Elektronik; Manufacturer Part Num: 150060BS75000
D3 D4 = LED_WURTH: LED YELLOW CLEAR 0603 SMD; Item Num: K21433-001; LIFECYCLE_PHASE: Active; Lead Free Status: Lead Free; Manufacturer: Kingbright; Manufacturer Part Num: APT1608SYCK; Num Pins: 2; PART_SUBCLASS: LEDS; Part Class: LEDS; RoHS Compliant: RoHS Compliant
D5 = LED_WURTH: LED -SUPER RED, VF=1.9V, IF=0.03A, 0603; Item Num: K15376-001; LIFECYCLE_PHASE: Active; Lead Free Status: Lead Free; Manufacturer: Wurth Electroniks; Manufacturer Part Num: 150060SS75000; Num Pins: 2; PART_SUBCLASS: LEDS; Part Class: LEDS; RoHS Compliant: RoHS Compliant
D6-D12 D24 D25 = LED_WURTH: LED - BRIGHT GREEN, VF=2V, IF=0.03A, 0603; Item Num: K15375-001; LIFECYCLE_PHASE: Active; Lead Free Status: Lead Free; Manufacturer: Wurth Electroniks; Manufacturer Part Num: 150060VS75000; Num Pins: 2; PART_SUBCLASS: LEDS; Part Class: LEDS; RoHS Compliant: RoHS Compliant
MTH1-MTH11 = MNT_HOLE_1
Q4 Q7-Q15 Q19 Q20 = PWRMOSFET_EN_GSD_0: IC, MOSFET, N-Channel, 20V; Item Num: K21465-001; Manufacturer: Fairchild
R394 = Resistor,_0402: RES SMD 2K OHM 1% 1/16W 0402; Item Num: J43524-001; Lead Free Status: Yes; Manufacturer: Panasonic; Manufacturer Part Num: ERJ-2RKF2001X; Num Pins: 2; Part Class: RESISTORS; Power Rating: 1/16W; RoHS Compliant: Yes
R395 = RESISTOR: RES ZERO OHM 1/16W 5% 0402 SMD; IPN: A93549-001; Item Num: A93549-001; Lead Free Status: Yes; Manufacturer: Yageo; Manufacturer Part Num: RC0402JR-070RL; Num Pins: 2; Part Class: RESISTORS; RoHS Compliant: Yes; Tolerance: 5%
R398 R429-R434 R438-R440 R442 R445 R447 R780 R6887 R6889 = RESISTOR: RES,10.0K OHMS,1.0%,1/16W, 0402; AGILE_LINK: http://sj-agile9app/Agile/PLMServlet?action=OpenEmailObject&classid=10000&objid=146548997; Item Num: K28115-001; LIFECYCLE_PHASE: Active; Lead Free Status: Yes; MFR_LIFECYCLE: Active; Manufacturer: Panasonic; Manufacturer Part Num: ERJ-2RKF1002X; Num Pins: 2; PART_SUBCLASS: RESISTORS; POWER: 1/16W; RoHS Compliant: Yes; TOLERANCE: 1%
R399 = RESISTOR: RES SMD 49.9 OHM 1% 1/10W 0402; Item Num: K16545-001; LIFECYCLE_PHASE: Active; Lead Free Status: Yes; MFR_LIFECYCLE: Active; Manufacturer: NIC Components Corp.; Manufacturer Part Num: NRC04F49R9TRF; Num Pins: 2; PART_SUBCLASS: RESISTORS; POWER: 1/16W; Part Class: Resistors; RoHS Compliant: Yes; Tolerance: 1%
R400-R403 = RESISTOR: RES 200 OHM 1/16W 5% 0402 SMD; Item Num: K15618-001; Manufacturer: Panasonic; Manufacturer Part Num: ERJ-2GEJ201X; Num Pins: 2; Part Class: RESISTORS; RoHS Compliant: Yes; Tolerance: 5%
R404-R407 R411 R6888 R6890 = RESISTOR_0: RES,56.2 OHMS,1.0%,1/16W,0402; Item Num: K16543-001; Lead Free Status: No; Manufacturer: Panasonic; Manufacturer Part Num: ERJ-2RKF56R2X; Num Pins: 2; Part Class: RESISTORS; Price: 0; RoHS Compliant: Yes; Tolerance: 1%
R418 R422 R425 R427 R428 R766 R767 R777 = RESISTOR: RES,1.00K OHMS,1.0%,1/16W,0402; Item Num: G60609-021; Lead Free Status: Yes; Manufacturer: Panasonic; Manufacturer Part Num: ERJ-2RKF1001X; Num Pins: 2; Part Class: Resistors; TOLERANCE: 1%
R822-R825 R833 R834 R836 R837 = RESISTOR: CHIP RESISTOR, 0402, 1%,51.1K OHM, 1/10W; AGILE_LINK: http://sj-agile9app/Agile/PLMServlet?action=OpenEmailObject&classid=10000&objid=146548997; Item Num: M58194-001; LIFECYCLE_PHASE: Active; Lead Free Status: Yes; MFR_LIFECYCLE: Active; Manufacturer: Panasonic; Manufacturer Part Num: ERJ-2RKF5112X; Num Pins: 2; PART_SUBCLASS: RESISTORS; POWER: 1/10W; RoHS Compliant: Yes; TOLERANCE: 1%
S1-S4 S6 = TS-A02SA-2-S100_0: SWITCH - PUSH BUTTON 6.0X3.5MM SND; Device: S7; Item Num: J43364-001; Lead Free Status: Yes; Manufacturer: Wurth Elektroniks; Manufacturer Part Num: 434121043816; Num Pins: 2; Part Class: Switches; RoHS Compliant: Yes
U89 U90 = NLSX4014MUTAG: IC, LEVEL TRANSLATOR; Item Num: M59362-001; Manufacturer: ON-SEMI
R435-R437 R441 R443 R444 R446 = RESISTOR: RES,10.0K OHMS,1.0%,1/16W, 0402; AGILE_LINK: http://sj-agile9app/Agile/PLMServlet?action=OpenEmailObject&classid=10000&objid=146548997; Item Num: K28115-001; LIFECYCLE_PHASE: Active; Lead Free Status: Yes; MFR_LIFECYCLE: Active; Manufacturer: Panasonic; Manufacturer Part Num: ERJ-2RKF1002X; Num Pins: 2; PART_SUBCLASS: RESISTORS; POWER: 1/16W; RESISTANCE: 10.0K; RoHS Compliant: Yes; TOLERANCE: 1%
U44 U46 = M24128: IC EEPROM 128KBIT 400KHZ 8SO; IPN: K21780-001; Item Num: K21780-001; Manufacturer: STMicroelectronics
U45 = W25Q64JVSSIM: SERIAL_NORFLASH,SPI,64MBIT,2.7V~3.6V,SOIC; Item Num: M21738-001; Manufacturer: Winbond
C492 = CAP: CAP - CER 4700PF 50V 10% X7R 0402; AGILE_LINK: http://sj-agile9app/Agile/PLMServlet?action=OpenEmailObject&classid=10000&objid=215384813; Item Num: G24897-001; LIFECYCLE_PHASE: Active; Lead Free Status: Lead Free; MFR_LIFECYCLE: Active; Manufacturer: Murata; Manufacturer Part Num: GRM155R71H472KA01D; Num Pins: 2; PACKAGING: Tape & Reel (TR); PART_SUBCLASS: CAPACITORS; RATED_VOLTAGE: 50V; RoHS Compliant: RoHS Compliant; Supplier Part Num: GRM155R71H472KA01D; Temperature Coefficient: X7R; Tolerance: 10%
C493 C494 = CAP: CAPC,C0G,0402,12.000PF,50.000V,+/- 5%; AGILE_LINK: http://sj-agile9app/Agile/PLMServlet?action=OpenEmailObject&classid=10000&objid=257385742; Item Num: A36095-043; LIFECYCLE_PHASE: Active; Lead Free Status: Lead Free; MFR_LIFECYCLE: Active; Manufacturer: Murata; Manufacturer Part Num: GRM1555C1H120JA01F; Num Pins: 2; PART_SUBCLASS: CAPACITORS; RATED_VOLTAGE: 50V; RoHS Compliant: RoHS Compliant; TOLERANCE: +/-5%; Temperature Coefficient: C0G
C495 C526-C529 C1044 = CAP: CAP CER 22UF 6.3V X6S 0603; AGILE_LINK: http://sj-agile9app/Agile/PLMServlet?action=OpenEmailObject&classid=10000&objid=257560276; Item Num: H63299-001; LIFECYCLE_PHASE: Active; Lead Free Status: Not Lead Free; MFR_LIFECYCLE: Active; Manufacturer: Murata; Manufacturer Part Num: GRM188C80J226ME15D; Num Pins: 2; PART_SUBCLASS: CAPACITORS; RATED_VOLTAGE: 6.3V; RoHS Compliant: RoHS Compliant; TOLERANCE: 20%; Temperature Coefficient: X6S
FB30 = BEAD_FERRITE_SM: FERRITE BEAD 600 OHM, 0.5A, 0.35 DCR, 0603 1LN; Item Num: G73133-001; LIFECYCLE_PHASE: Active; MFR_LIFECYCLE: Active; Manufacturer: Murata; Manufacturer Part Num: BLM18EG601SN1D; Num Pins: 2; Part Class: Inductors; RoHS Compliant: Yes
J10 = MICRO_USB_CONN: RECEPTACLE, USB 3.0, MICRO B, R/A; Item Num: G68794-001; Lead Free Status: Yes; MFR_LIFECYCLE: Active; Manufacturer: Molex; Manufacturer Part Num: 47589-0001; Num Pins: 9; Part Class: Connectors; RoHS Compliant: Yes
R448 = RESISTOR: RES 20.0K OHM 1/16W 1% 0402 SMD; Item Num: A78608-001; Lead Free Status: Yes; Manufacturer: Panasonic; Manufacturer Part Num: ERJ-2RKF2002X; Num Pins: 2; Part Class: RESISTORS; RoHS Compliant: Yes; Tolerance: 1%
R450 = RES_0_OHM_5%_1_16W_0402_SMD: IPN: A93549-001; Item Num: A93549-001; Lead Free Status: Yes; Manufacturer: Yageo; Manufacturer Part Num: RC0402JR-070RL; Num Pins: 2; Part Class: RESISTORS; RoHS Compliant: Yes; Tolerance: 5%
R451 R452 = RESISTOR: RES SMD 2K OHM 1% 1/16W 0402; Item Num: J43524-001; Lead Free Status: Yes; Manufacturer: Panasonic; Manufacturer Part Num: ERJ-2RKF2001X; Num Pins: 2; Part Class: RESISTORS; Power Rating: 1/16W; RoHS Compliant: Yes; Tolerance: 1%
R453 = RESISTOR: RES ZERO OHM 1/16W 5% 0402 SMD; Item Num: A93549-001; Lead Free Status: No; Manufacturer: Yageo; Manufacturer Part Num: RC0402JR-070RL; Num Pins: 2; Part Class: RESISTORS; RoHS Compliant: Yes; Tolerance: 5%
R454 = RESISTOR: RES, 22 OHMS, 5%, 1/16W, 0402; AGILE_LINK: http://sj-agile9app/Agile/PLMServlet?action=OpenEmailObject&classid=10000&objid=218074840; Item Num: K15613-001; LIFECYCLE_PHASE: Active; MFR_LIFECYCLE: Active; Manufacturer: NIC Components Corp.; Manufacturer Part Num: NRC04J220TRF; Num Pins: 2; PART_SUBCLASS: RESISTORS; POWER: 1/16W; RoHS Compliant: RoHS Compliant; TOLERANCE: 5%
U47 = MAX811: IC - MPU V-MONITOR 2.93V, RESET/POWER-ON RESET, SOT143-4; Item Num: D16587-001; Lead Free Status: Yes; Manufacturer: Maxim Integrated Products; Manufacturer Part Num: MAX811SEUS+T; Num Pins: 4; Part Class: ICs; RoHS Compliant: Yes
U48 = TPD2EUSB30: DIODE - FULL SPEED USB ESD SOLUTION, 2CH, SOT3; Item Num: K12736-001; Lead Free Status: Yes; MFR_LIFECYCLE: Active; Manufacturer: Texas Instruments; Manufacturer Part Num: TPD2EUSB30DRxx; Num Pins: 3; Part Class: ICS; RoHS Compliant: Yes
U49 = CY7C68013A_56QFN: IC - EZ-USB FX2LP Microcontroller 400KHz, 56-QFN, 3.3V; Item Num: K33816-001; Lead Free Status: Yes; Manufacturer: Cypress; Manufacturer Part Num: CY7C68013A-56LTXCx; Num Pins: 57; Part Class: ICs; RoHS Compliant: Yes
Y2 = CRYSTAL_SM_13: CRYSTAL - MINI XTL, 24.00 MHZ, +/-50PPM, +/-30PPM-20~75C, 12PF, 2.0mm x 1.6mm SMD; Item Num: K15535-001; Lead Free Status: Yes; MFR_LIFECYCLE: Active; Manufacturer: Epson Toyocom; Manufacturer Part Num: FA-128 24.0000MB-W; Num Pins: 4; RoHS Compliant: Yes
C504-C509 C514-C517 C1032-C1037 = CAP: CAP CER 100UF 6.3V X5R 0805; Item Num: K32109-001; Lead Free Status: Lead Free; Manufacturer: Murata Electronics North America; Manufacturer Part Num: GRM21BR60J107ME15L; Num Pins: 2; PART_SUBCLASS: CAPACITORS; Part Class: CAPACITORS; RATED_VOLTAGE: 6.3V; RoHS Compliant: RoHS Compliant; Temperature Coefficient: X5R
C510-C513 C518-C521 C1038-C1041 = CAP: CAP CER 47UF 6.3V X5R 0603; IPN: 602433-109; Item Num: K31624-001; MFR_LIFECYCLE: Active; Manufacturer: Murata Electronics North America; Manufacturer Part Num: GRM188R60J476ME15D; Num Pins: 2; PART_SUBCLASS: CAPACITORS; RATED_VOLTAGE: 6.3V; RoHS Compliant: RoHS Compliant; TOLERANCE: 20%; Temperature Coefficient: X5R
C522 C523 C580 C581 C588-C591 C1045 C1046 C1074-C1079 = CAP: CAP CER 47UF 4V X6S 0805; AGILE_LINK: http://sj-agile9app/Agile/PLMServlet?action=OpenEmailObject&classid=10000&objid=257560276; Item Num: C95333-006; LIFECYCLE_PHASE: Active; Lead Free Status: Not Lead Free; MFR_LIFECYCLE: Active; Manufacturer: Taiyo Yuden; Manufacturer Part Num: AMK212BC6476MG-T; Num Pins: 2; PART_SUBCLASS: CAPACITORS; RATED_VOLTAGE: 4V; RoHS Compliant: RoHS Compliant; TOLERANCE: 20%; Temperature Coefficient: X6S
C524 C533-C541 C548 C549 C574-C579 C582-C587 C1042 C1043 C1070 C1071 = CAP: CAP CER 10UF 6.3V X5R 0402; Item Num: K46607-001; LIFECYCLE_PHASE: Active; Lead Free Status: Lead Free; MFR_LIFECYCLE: Active; Manufacturer: Murata Electronics North America; Manufacturer Part Num: GRJ155R60J106ME11D; Num Pins: 2; PART_SUBCLASS: CAPACITORS; Part Class: CAPACITORS; RATED_VOLTAGE: 6.3V; RoHS Compliant: RoHS Compliant; TOLERANCE: 20%; Temperature Coefficient: X5R
C525 C530 C542-C544 C550-C552 C561 C562 C571 C1047 C1048 C1072 C1224 = CAP: CAP - CER 1UF 6.3V 20% X5R 0201; Item Num: C83410-013; Lead Free Status: Yes; Manufacturer: TDK; Manufacturer Part Num: C0603X5R0J105M; Num Pins: 2; Part Class: CAPACITORS; RoHS Compliant: Yes; Temperature Coefficient: X5R; Working Voltage: 6.3V
C545 C546 C572 C573 C1049-C1069 C1073 = CAP: CAP - CER 4.7UF, +/-20%, 6.3V, X5R, 0402; IPN: A36096-107; Item Num: A36096-107; Manufacturer: Murata; Manufacturer Part Num: GRM155R60J475ME87D; Temperature Coefficient: X5R; Tolerance: +/-20%; Voltage: 6.3V
C1238-C1257 = CAP: CAP CER 100UF 6.3V X6T 1206; CLASS: DISCRETE; Dielectric Type: X6T; Item Num: H65271-004; LIFECYCLE_PHASE: Active; Lead Free Status: Lead Free; MFR_LIFECYCLE: Active; Manufacturer: Murata; Manufacturer PN: GRM31CD80J107ME39L; Manufacturer Part Num: GRM31CR60J107ME39L; Num Pins: 2; PART_SUBCLASS: CAPACITORS; RATED_VOLTAGE: 6.3V; Rated Voltage: 6.3V; RoHS Compliant: RoHS Compliant; Temperature Coefficient: X6T; Tolerance: 20%; Working Voltage: 6.3V
C1258 C1259 = CAP: CAP CER 220UF 4V X6S 1210; CLASS: DISCRETE; Dielectric Type: X6S; IPN: xxxxxx-xxx; Item Num: D38464-012; Manufacturer: Murata; Manufacturer PN: GRM32EC80G227ME05L; Manufacturer Part Num: GRM32EC80G227ME05L; Rated Voltage: 4V; Temperature Coefficient: X6S; Tolerance: 20%; Working Voltage: 4V
C1260-C1289 = CAP: CAP CER 10UF 6.3V X5R 0402; AGILE_LINK: http://sj-agile9app/Agile/PLMServlet?action=OpenEmailObject&classid=10000&objid=257560276; Item Num: K46607-001; LIFECYCLE_PHASE: Active; Lead Free Status: Lead Free; MFR_LIFECYCLE: Active; Manufacturer: Murata Electronics North America; Manufacturer Part Num: GRJ155R60J106ME11D; Num Pins: 2; PART_SUBCLASS: CAPACITORS; Part Class: CAPACITORS; RATED_VOLTAGE: 6.3V; RoHS Compliant: RoHS Compliant; TOLERANCE: 20%; Temperature Coefficient: X5R

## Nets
2V5_DDR4_DIMM: C470.1 C473.2 R376.2 R377.2 R383.2 R384.2 R385.1 R6897.1 U38.2(VREF1) ; also on sheet 54 55 56
3V3_STBY: C487.1 C488.2 FB30.2 R399.2 R429.2 R430.2 R431.2 R432.2 R433.2 R434.2 R767.1 R777.1 R780.2 R6888.2 R6890.2 U44.8(VCC) U45.8(VCC) ; also on sheet 8 10 16 22 28 32 34 40 41 48 49 50 51 52 53 54 58
3V3_SYS: C471.2 C489.1 C1023.2 C1025.2 R368.2 R369.2 R378.2 R379.2 R380.1 R400.2 R401.2 R402.2 R403.2 R404.2 R405.2 R406.2 R407.2 R411.2 R422.1 R439.2 R440.2 R441.2 U46.8(VCC) U89.11(VCC) U90.11(VCC) ; also on sheet 29 30 31 32 34 41
3V3_USBPHY: C490.2 C495.2 C496.2 C497.2 C498.2 C499.2 C500.2 C501.2 C502.2 C503.2 FB30.1 R446.1 R451.2 R452.2 U47.4(VCC) U49.3(AVCC) U49.7(AVCC) U49.11(VCC) U49.17(VCC) U49.27(VCC) U49.32(VCC) U49.43(VCC) U49.55(VCC)
5V0: R394.2 ; also on sheet 43 44 45 46 47 58
GND: C466.2 C467.1 C470.2 C471.1 C472.2 C473.1 C482.1 C483.1 C484.2 C485.1 C486.1 C487.2 C488.1 C489.2 C490.1 C491.2 C492.2 C493.2 C494.2 C495.1 C496.1 C497.1 C498.1 C499.1 C500.1 C501.1 C502.1 C503.1 C504.2 C505.2 C506.2 C507.2 C508.2 C509.2 C510.2 C511.2 C512.2 C513.2 C514.2 C515.2 C516.2 C517.2 C518.2 C519.2 C520.2 C521.2 C522.1 C523.1 C524.2 C525.1 C526.1 C527.1 C528.1 C529.1 C530.1 C533.2 C534.2 C535.2 C536.2 C537.2 C538.2 C539.2 C540.2 C541.2 C542.1 C543.1 C544.1 C545.2 C546.2 C548.2 C549.2 C550.1 C551.1 C552.1 C561.1 C562.1 C571.1 C572.2 C573.2 C574.2 C575.2 C576.2 C577.2 C578.2 C579.2 C580.1 C581.1 C582.2 C583.2 C584.2 C585.2 C586.2 C587.2 C588.1 C589.1 C590.1 C591.1 C1003.1 C1022.2 C1023.1 C1024.2 C1025.1 C1032.2 C1033.2 C1034.2 C1035.2 C1036.2 C1037.2 C1038.2 C1039.2 C1040.2 C1041.2 C1042.2 C1043.2 C1044.1 C1045.1 C1046.1 C1047.1 C1048.1 C1049.2 C1050.2 C1051.2 C1052.2 C1053.2 C1054.2 C1055.2 C1056.2 C1057.2 C1058.2 C1059.2 C1060.2 C1061.2 C1062.2 C1063.2 C1064.2 C1065.2 C1066.2 C1067.2 C1068.2 C1069.2 C1070.2 C1071.2 C1072.1 C1073.2 C1074.1 C1075.1 C1076.1 C1077.1 C1078.1 C1079.1 C1224.1 C1238.2 C1239.2 C1240.2 C1241.2 C1242.2 C1243.2 C1244.2 C1245.2 C1246.2 C1247.2 C1248.2 C1249.2 C1250.2 C1251.2 C1252.2 C1253.2 C1254.2 C1255.2 C1256.2 C1257.2 C1258.2 C1259.2 C1260.1 C1261.1 C1262.1 C1263.1 C1264.1 C1265.1 C1266.1 C1267.1 C1268.1 C1269.1 C1270.1 C1271.1 C1272.1 C1273.1 C1274.1 C1275.1 C1276.1 C1277.1 C1278.1 C1279.1 C1280.1 C1281.1 C1282.1 C1283.1 C1284.1 C1285.1 C1286.1 C1287.1 C1288.1 C1289.1 J10.5(GND) MTH4.1(GND) MTH6.1(GND) MTH11.1(GND) Q4.2(SOURCE) Q7.2(SOURCE) Q8.2(SOURCE) Q9.2(SOURCE) Q10.2(SOURCE) Q11.2(SOURCE) Q12.2(SOURCE) Q13.2(SOURCE) Q14.2(SOURCE) Q15.2(SOURCE) Q19.2(SOURCE) Q20.2(SOURCE) R395.1 R398.2 R426.1 R435.1 R436.1 R437.1 R438.2 R442.2 R443.1 R444.1 R445.1 R448.1 R449.1 R450.1 R453.2 R822.1 R823.1 R824.1 R825.1 R833.1 R834.1 R836.1 R837.1 R6887.1 R6889.1 R6896.1 R6897.2 S1.1 S2.1 S3.1 S4.1 S6.1 U36.1(GND) U38.1(GND) U39.1(GND) U44.4(GND) U45.4(GND) U46.4(GND) U47.1(GND) U48.3(GND) U49.6(AGND) U49.10(AGND) U49.12(GND) U49.14(RESERVED) U49.26(GND) U49.28(GND) U49.41(GND) U49.53(GND) U49.56(GND) U49.57(EXPOSED_PAD) U89.6(GND) U90.6(GND) Y2.2 Y2.4 ; also on sheet 8 9 10 11 12 13 15 16 19 20 21 22 23 24 25 26 27 28 29 30 31 32 33 34 40 41 42 43 44 45 46 47 48 49 50 51 52 53 54 55 56 58
GND_CHS: C492.1 J10.6(SHELL1) J10.7(SHELL2) J10.8(SHELL3) J10.9(SHELL4) R453.1
VBUS_5V: J10.1(VBUS) R447.1
24M_XTALIN: C493.1 U49.5(XTALIN) Y2.1
24M_XTALOUT: C494.1 U49.4(XTALOUT) Y2.3
CFG_IMAGE0: Q19.1(GATE) R6887.2 ; also on sheet 10
CFG_IMAGE1: Q20.1(GATE) R6889.2 ; also on sheet 10
CPU_RESETn: R418.2 R777.2 S1.2 ; also on sheet 10 34
CXL_PERSTn: R766.2 R767.2 S6.2 ; also on sheet 22 31 34
DDR4_2V5_DIMM_SCL: R376.1 R384.1 U38.3(SCL1) U39.6(SCL2) ; also on sheet 55 56
DDR4_2V5_DIMM_SDA: R377.1 R383.1 U38.4(SDA1) U39.5(SDA2) ; also on sheet 55 56
FPGA_1V2_SCL: R381.1 U39.3(SCL1) ; also on sheet 16
FPGA_1V2_SDA: R382.1 U39.4(SDA1) ; also on sheet 16
FPGA_1V8_CONF_DONE: Q15.1(GATE) ; also on sheet 10 11
FPGA_1V8_SVID_SCL: R366.1 U36.3(SCL1) ; also on sheet 11
FPGA_1V8_SVID_SDA: R367.1 U36.4(SDA1) ; also on sheet 11
FPGA_3V3_LED0: Q7.1(GATE) R822.2 ; also on sheet 34
FPGA_3V3_LED1: Q12.1(GATE) R823.2 ; also on sheet 34
FPGA_3V3_LED2: Q13.1(GATE) R824.2 ; also on sheet 34
FPGA_3V3_LED3: Q14.1(GATE) R825.2 ; also on sheet 34
FPGA_3V3_SCL: R379.1 U38.6(SCL2) U46.6(SCL) ; also on sheet 16 29 30
FPGA_3V3_SDA: R378.1 U38.5(SDA2) U46.5(SDA) ; also on sheet 16 29 30
FPGA_3V3_SVID_SCL: R369.1 U36.6(SCL2) ; also on sheet 42
FPGA_3V3_SVID_SDA: R368.1 U36.5(SDA2) ; also on sheet 42
FPGA_VCC: C504.1 C505.1 C506.1 C507.1 C508.1 C509.1 C510.1 C511.1 C512.1 C513.1 C514.1 C515.1 C516.1 C517.1 C518.1 C519.1 C520.1 C521.1 C1032.1 C1033.1 C1034.1 C1035.1 C1036.1 C1037.1 C1038.1 C1039.1 C1040.1 C1041.1 C1042.1 C1043.1 C1044.2 C1238.1 C1239.1 C1240.1 C1241.1 C1242.1 C1243.1 C1244.1 C1245.1 C1246.1 C1247.1 C1248.1 C1249.1 C1250.1 C1251.1 C1252.1 C1253.1 C1254.1 C1255.1 C1256.1 C1257.1 C1258.1 C1259.1 C1260.2 C1261.2 C1262.2 C1263.2 C1264.2 C1265.2 C1266.2 C1267.2 C1268.2 C1269.2 C1270.2 C1271.2 C1272.2 C1273.2 C1274.2 C1275.2 C1276.2 C1277.2 C1278.2 C1279.2 C1280.2 C1281.2 C1282.2 C1283.2 C1284.2 C1285.2 C1286.2 C1287.2 C1288.2 C1289.2 ; also on sheet 23 42 43 44 45 46
FPGA_VCC_HSSI_GXF: C522.2 C523.2 C526.2 C527.2 C528.2 C529.2 C542.2 C543.2 C574.1 C575.1 C580.2 C581.2 C582.1 C583.1 C1047.2 C1048.2 C1074.2 C1075.2 ; also on sheet 23 47
FPGA_VCCA_PLL: C548.1 C549.1 ; also on sheet 23
FPGA_VCCCLK_GXF: C1070.1 C1071.1 ; also on sheet 22 23
FPGA_VCCERT_FGT_GXF: C576.1 C577.1 C584.1 C585.1 C588.2 C589.2 C590.2 C591.2 C1076.2 C1077.2 C1078.2 C1079.2 C1224.2 ; also on sheet 23 49
FPGA_VCCFUSEWR_GXF: C1072.2 C1073.1 ; also on sheet 23 51
FPGA_VCCH_FGT_GXF: C578.1 C579.1 C586.1 C587.1 ; also on sheet 23
FPGA_VCCH_SDM: C530.2 C1045.2 C1046.2 ; also on sheet 23 48
FPGA_VCCIO_1V2: C472.1 C533.1 C534.1 C535.1 C536.1 C537.1 C538.1 C539.1 C540.1 C1022.1 C1024.1 C1054.1 C1055.1 C1056.1 C1057.1 C1058.1 C1059.1 C1060.1 C1061.1 C1062.1 C1063.1 C1064.1 C1065.1 C1066.1 C1067.1 C1068.1 C1069.1 R381.2 R382.2 U39.2(VREF1) U89.1(VL) U89.12(EN) U90.1(VL) U90.12(EN) ; also on sheet 10 16 23 25 26 27 31 34 50 54 55 56
FPGA_VCCIO_SDM_HPS: C466.1 C561.2 C562.2 C571.2 R366.2 R367.2 R6896.2 U36.2(VREF1) ; also on sheet 11 23 28 33 52 53
FPGA_VCCPLL: C550.2 C551.2 C552.2 C1050.1 C1051.1 C1052.1 C1053.1 ; also on sheet 23
FPGA_VCCPLLDIG_HPS: C525.2 ; also on sheet 23
FPGA_VCCPLLDIG_SDM: C544.2 ; also on sheet 23
FPGA_VCCPT: C524.1 C545.1 C546.1 C1049.1 ; also on sheet 23 28 50 51
FPGA_VCCR_CORE: C541.1 C572.1 C573.1 ; also on sheet 23 49
FX2_D_N: J10.2(D-) U48.2(D-) U49.9(DMINUS)
FX2_D_P: J10.3(D+) U48.1(D+) U49.8(DPLUS)
FX2_FLAGA: U49.29(CTL0) ; also on sheet 10
FX2_FLAGB: U49.30(CTL1) ; also on sheet 10
FX2_FLAGC: U49.31(CTL2) ; also on sheet 10
FX2_PA0: U49.33(PA0) ; also on sheet 10
FX2_PA1: U49.34(PA1) ; also on sheet 10
FX2_PA2: U49.35(PA2) ; also on sheet 10
FX2_PA3: U49.36(PA3) ; also on sheet 10
FX2_PA4: U49.37(PA4) ; also on sheet 10
FX2_PA5: U49.38(PA5) ; also on sheet 10
FX2_PA6: U49.39(PA6) ; also on sheet 10
FX2_PA7: U49.40(PA7) ; also on sheet 10
FX2_PB0: U49.18(PB0) ; also on sheet 10
FX2_PB1: U49.19(PB1) ; also on sheet 10
FX2_PB2: U49.20(PB2) ; also on sheet 10
FX2_PB3: U49.21(PB3) ; also on sheet 10
FX2_PB4: U49.22(PB4) ; also on sheet 10
FX2_PB5: U49.23(PB5) ; also on sheet 10
FX2_PB6: U49.24(PB6) ; also on sheet 10
FX2_PB7: U49.25(PB7) ; also on sheet 10
FX2_PD0: U49.45(PD0) ; also on sheet 10
FX2_PD1: U49.46(PD1) ; also on sheet 10
FX2_PD2: U49.47(PD2) ; also on sheet 10
FX2_PD3: U49.48(PD3) ; also on sheet 10
FX2_PD4: U49.49(PD4) ; also on sheet 10
FX2_PD5: U49.50(PD5) ; also on sheet 10
FX2_PD6: U49.51(PD6) ; also on sheet 10
FX2_PD7: U49.52(PD7) ; also on sheet 10
FX2_RESETn: R449.2 U47.2(~{RESET}) U49.42(~{RESET}) ; also on sheet 10
FX2_SCL: R451.1 U49.15(SCL) ; also on sheet 10
FX2_SDA: R452.1 U49.16(SDA) ; also on sheet 10
FX2_SLRDn: U49.1(RDY0) ; also on sheet 10
FX2_SLWRn: U49.2(RDY1) ; also on sheet 10
FX2_WAKEUP: C491.1 R446.2 R447.2 R448.2 U49.44(WAKEUP)
GXF_2ND_PERSTn: R428.2 S4.2 ; also on sheet 10 22 34
HPS_RESETn: R422.2 R425.2 S2.2 ; also on sheet 10
MAX_I2C_SCL: U44.6(SCL) ; also on sheet 8 10 32 33 34 40 42 49 50
MAX_I2C_SDA: U44.5(SDA) ; also on sheet 8 10 32 33 34 40 42 49 50
NIOS_CLK: U45.6(CLK) ; also on sheet 10
NIOS_CSn: R432.1 U45.1(~{CS}) ; also on sheet 10
NIOS_IO0: U45.5(DI/IO0) ; also on sheet 10
NIOS_IO1: U45.2(DO/IO1) ; also on sheet 10
NIOS_IO2: R433.1 U45.3(~{WP}/IO2) ; also on sheet 10
NIOS_IO3: R434.1 U45.7(~{RST}/~{HLD}/IO3) ; also on sheet 10
OVERTEMP_LEDn: D5.C(CATHODE) R780.1 ; also on sheet 10
PCIE_PERSTn: R427.2 S3.2 ; also on sheet 22
PWRGD_OUT: Q4.1(GATE) R398.1 ; also on sheet 10
QSFP_1V2_LED1: U90.3(IO_VL2) ; also on sheet 16
QSFP_1V2_LED2: U90.4(IO_VL3) ; also on sheet 16
QSFP_LED1: Q11.1(GATE) R837.2 U90.9(IO_VCC2)
QSFP_LED2: Q10.1(GATE) R836.2 U90.8(IO_VCC3)
QSFPDD_1V2_LED1: U89.3(IO_VL2) ; also on sheet 16
QSFPDD_1V2_LED2: U89.4(IO_VL3) ; also on sheet 16
QSFPDD_LED1: Q9.1(GATE) R834.2 U89.9(IO_VCC2)
QSFPDD_LED2: Q8.1(GATE) R833.2 U89.8(IO_VCC3)
SVID_ENABLE: R370.1 ; also on sheet 10
U38_VREF2: R380.2 U38.7(VREF2) U38.8(EN)
U39_VREF2: R385.2 U39.7(VREF2) U39.8(EN)
USB_DISABLEn: U47.3(~{MR}) ; also on sheet 10
USB_T_CLK: R454.1 ; also on sheet 10
N756713: D8.C(CATHODE) Q7.3(DRAIN)
N756717: D8.A(ANODE) R404.1
N756805: D2.C(CATHODE) Q4.3(DRAIN) R395.2
N756817: D2.A(ANODE) R394.1
N756925: D9.C(CATHODE) Q12.3(DRAIN)
N756929: D9.A(ANODE) R405.1
N757065: D10.C(CATHODE) Q13.3(DRAIN)
N757069: D10.A(ANODE) R406.1
N757157: D5.A(ANODE) R399.1
N757219: D11.C(CATHODE) Q14.3(DRAIN)
N757223: D11.A(ANODE) R407.1
N757357: C482.2 R418.1
N757409: D12.C(CATHODE) Q15.3(DRAIN)
N757413: D12.A(ANODE) R411.1
N757643: C483.2 R425.1
N757741: C485.2 R427.1
N757839: C486.2 R428.1
N757891: C484.1 MTH2.1(GND) MTH7.1(GND) R426.2
N1009139: J10.4(ID) R450.2
N1009759: R454.2 U49.13(IFCLK)
N1028872: R429.1 R435.2 U44.3(E2)
N1028876: R430.1 R436.2 U44.2(E1)
N1028880: R431.1 R437.2 U44.1(E0)
N1029030: R438.1 U44.7(WC_N)
N1137042: R439.1 R443.2 U46.3(E2)
N1137046: R440.1 R444.2 U46.2(E1)
N1137050: R441.1 R445.2 U46.1(E0)
N1137200: R442.1 U46.7(WC_N)
N2008530: C467.2 R370.2 U36.7(VREF2) U36.8(EN)
N2766693: D3.C(CATHODE) Q8.3(DRAIN)
N2766701: D3.A(ANODE) R400.1
N2766729: D6.C(CATHODE) Q9.3(DRAIN)
N2766737: D6.A(ANODE) R401.1
N2801539: D4.C(CATHODE) Q10.3(DRAIN)
N2801547: D4.A(ANODE) R402.1
N2801575: D7.C(CATHODE) Q11.3(DRAIN)
N2801583: D7.A(ANODE) R403.1
N5402274: C1003.2 R766.1
N7208051: D24.C(CATHODE) Q19.3(DRAIN)
N7208055: D24.A(ANODE) R6888.1
N7208455: D25.C(CATHODE) Q20.3(DRAIN)
N7208459: D25.A(ANODE) R6890.1

Not connected (* = marked no-connect by the designer): MTH1 1(GND)*; MTH3 1(GND)*; MTH5 1(GND)*; MTH8 1(GND)*; MTH9 1(GND)*; MTH10 1(GND)*; U49 54(CLKOUT)*; U89 2(IO_VL1)* 5(IO_VL4)* 7(IO_VCC4)* 10(IO_VCC1)*; U90 2(IO_VL1)* 5(IO_VL4)* 7(IO_VCC4)* 10(IO_VCC1)*

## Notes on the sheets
sheet 35
- For LDO Sink
  Current
- Channel Icc = 128mA max
- Pull-ups on
  pg 46
- SCL/SDA are Hi-Z
  when EN is low
- For LDO Sink
  Current
- Channel Icc = 128mA max
- Channel Icc = 128mA max
- SCL/SDA are Hi-Z
  when EN is low
- SCL/SDA are Hi-Z
  when EN is low
sheet 36
- LEDs And PushButtons
- POWER LED
- VGS(th) = 0.6V / 1V /1.5V
- EN:
  VIH = 0.96V
  VIL = 0.24V
  Absmax = 5.5V
- EN:
  VIH = 0.96V
  VIL = 0.24V
  Absmax = 5.5V
- VGS(th) = 0.6V / 1V /1.5V
- VGS(th) = 0.6V / 1V /1.5V
- Large Mounting holes on the rear of board
- Large Mounting holes on the front of board
- Large Mounting holes for heatsink
- Large Mounting holes for IO48 Daughter Card
- Pullup on pg22
- Pullup on pg22
- DNI cap loading for U33
  to work properly
sheet 37
- NIOS Flash
- MAC EEPROM
- VCC = 2.7V - 3.6V
  Absmax = 4.6V
- Addr = 0x57/0x5F
- Pull-ups on PG35
- I2C:
  AbsMax = 6.5V
  Vih_min = 0.7 x VCC = 2.31V
  Vil_max = 0.3 x VCC = 0.99V
- CERT EEPROM
- Addr = 0x56/0x5E
- Pull-ups on PG38
- I2C:
  AbsMax = 6.5V
  Vih_min = 0.7 x VCC = 2.31V
  Vil_max = 0.3 x VCC = 0.99V
- Vih = 0.7VCC = 2.31V
  Vil = 0.3VCC = 0.99V
sheet 38
- USB-BlasterII Phy
- IFCLK = 48MHz
- PLACE NEAR CY7C68013A
sheet 39
- FPGA Core Decoupling
- Place on TOP Side
- Place on BOT Side
- Place these caps around FPGA pin field for VCC, VCCP
- Place TOP near
  VCCH pins
- Place TOP near
  VCCPT pins
- Place these caps within FPGA cavity for VCC, VCCP
- Place bot near
  VCCL_HPS pins
- Place these caps around FPGA pin field for VCC, VCCP
- Place TOP near
  VCCR_CORE pins
- Place TOP near
  VCCL_HPS pins
- Place near
  VCCHPLLDIG_HPS pin
- Place these caps within
  FPGA cavity for VCCH
- Place near
  VCCH_SDM pin
- Place near
  VCCL_SDM pin
- Place near VCCIO_1V2 pins
- Place TOP near
  VCCH_SDM pins
- Place near
  VCCPLLDIG_SDM pin
- Place near
  VCCPT pin
- Place near
  VCCADC pin
- Place near
  VCCA_PLL pin
- Extra FPGA VCC Caps -- Place on BOT side
  periphery, 2-GND vias each cap gnd pad minimum
- Place near
  VCCPLL_SDM pin
- Place near VCCIO_1V2 pins
- Place near
  VCCPLL_SDM pin
- Place near 1ea near
  VCCIO_SDM, VCCIO_HPS
- Place near VCCIO_1V2 pins
- Place near
  VCCPLL_HPS pin
- Extra FPGA VCC Caps -- Place on BOT side
   in BGA field between PWR/GND vias
- Place BOT at
  FPGA Remote
  Sense Point
- Place near
  VCCFUSEWR_SDM pin
- Place TOP near
  VCCR_CORE pins
- FPGA F-Tile Decoupling
- Place on BOT Side
- Place on TOP Side
- Place on left side near F-Tile Bank 12C
- Place on left side near F-Tile Bank 13A
- Place BOT near
  VCC_HSSI_GXF pins
- Place BOT near
  VCC_ERT_FGT_GXF pins
- Place BOT near
  VCCH_FGT_GXF pins
- Place on left side near F-Tile Bank 12C
- Place on left side near F-Tile Bank 13A
- Place BOT near
  VCC_HSSI_GXF pins
- Place BOT near
  VCC_ERT_FGT_GXF pins
- Place BOT near
  VCCH_FGT_GXF pins
- Place on left side near F-Tile Bank 13A
- Place on left side near F-Tile Bank 12C
- Place BOT near
  VCCCLK_GXF pins
- Place near
  VCCFUSEWR_GXF pin
- Place near
  VCCFUSECORE_GXF pin
